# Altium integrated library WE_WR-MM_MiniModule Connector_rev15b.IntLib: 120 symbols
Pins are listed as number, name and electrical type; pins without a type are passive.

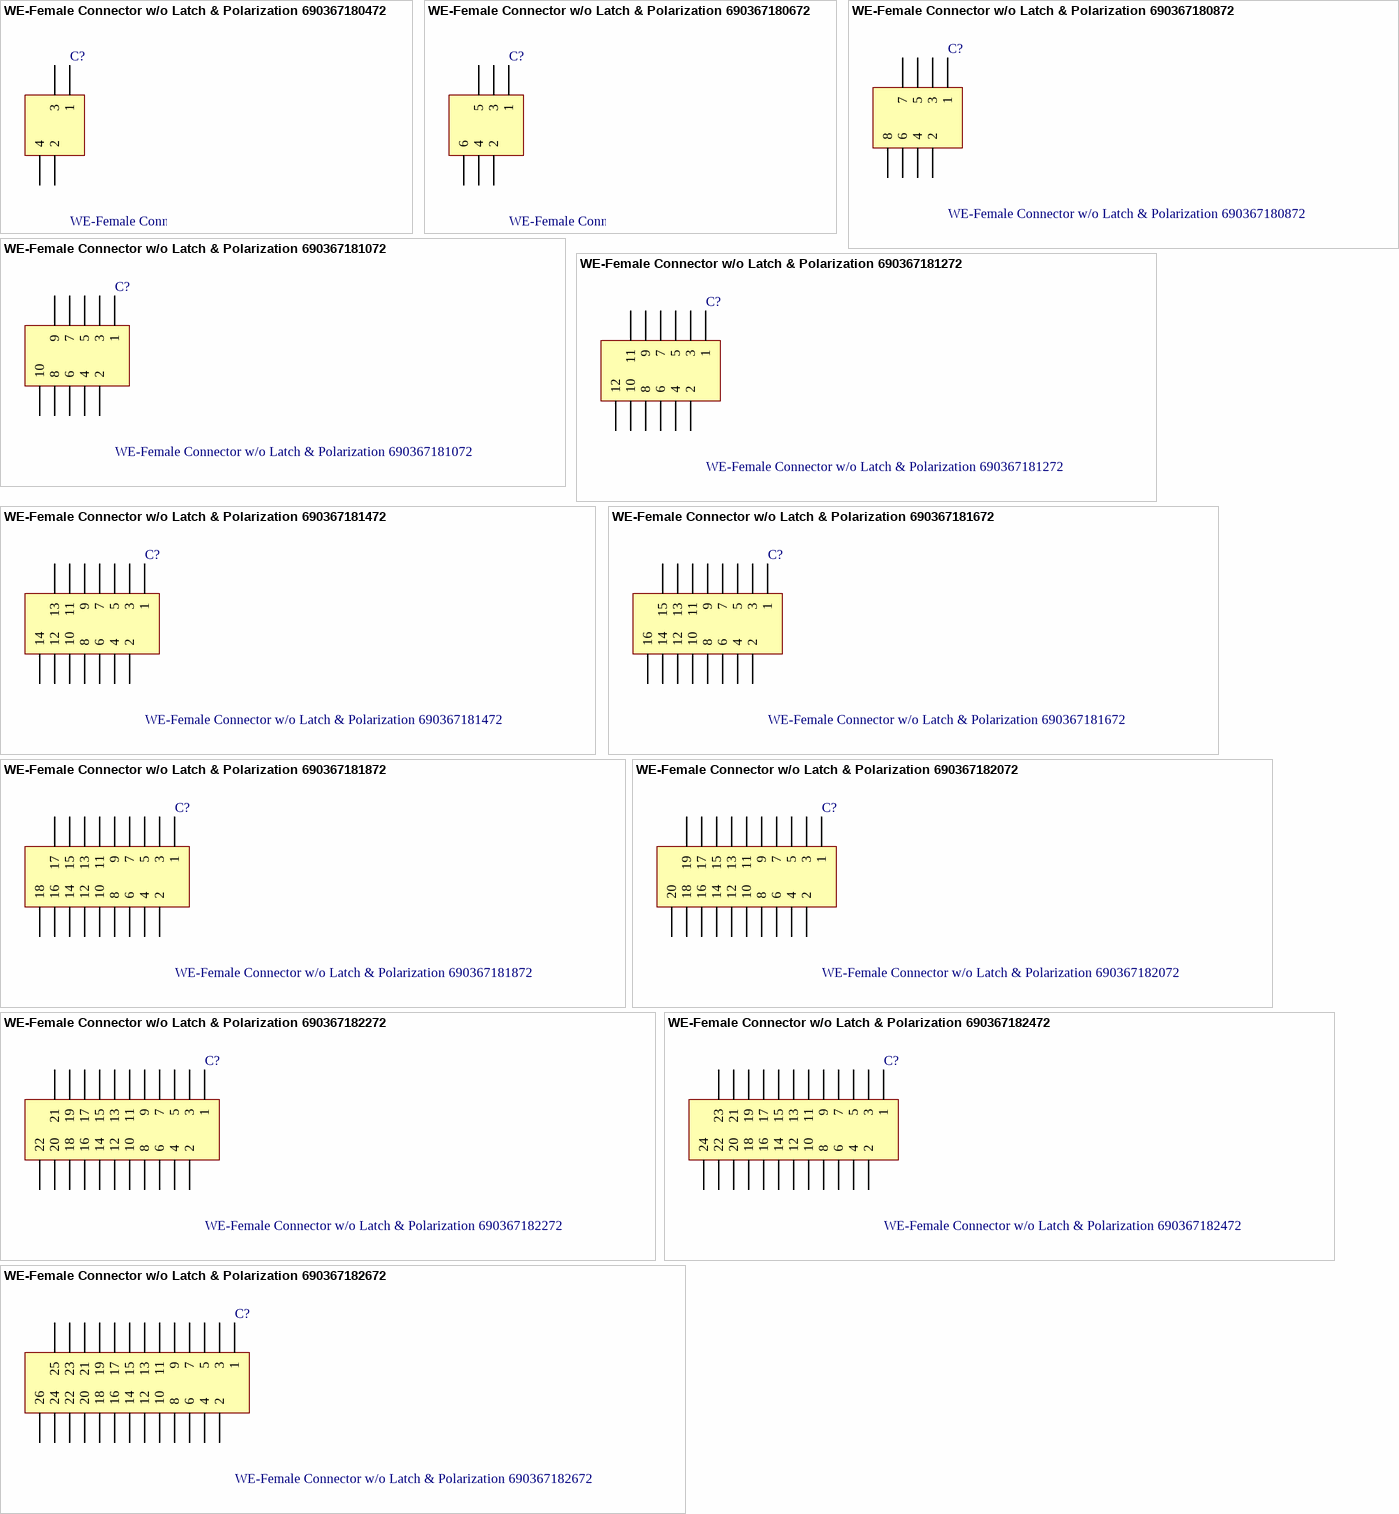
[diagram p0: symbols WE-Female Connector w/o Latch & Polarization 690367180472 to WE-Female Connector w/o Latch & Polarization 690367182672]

## WE-Female Connector w/o Latch & Polarization 690367180472
designator C?
WR-MM Female Connector w/o Latch & Polarization; Manufacturer: Würth Elektronik eiSos GmbH; ComponentLink1 Description: Manufacturer; ComponentLink2 Description: Datasheet; NoPins: 4
footprint 690367180472 (4 pins, straight)
pins: 1, 2, 3, 4

## WE-Female Connector w/o Latch & Polarization 690367180672
designator C?
WR-MM Female Connector w/o Latch & Polarization; Manufacturer: Würth Elektronik eiSos GmbH; ComponentLink1 Description: Manufacturer; ComponentLink2 Description: Datasheet; NoPins: 6
footprint 690367180672 (6 pins, straight)
pins: 1, 2, 3, 4, 5, 6

## WE-Female Connector w/o Latch & Polarization 690367180872
designator C?
WR-MM Female Connector w/o Latch & Polarization; Manufacturer: Würth Elektronik eiSos GmbH; ComponentLink1 Description: Manufacturer; ComponentLink2 Description: Datasheet; NoPins: 8
footprint 690367180872 (8 pins, straight)
pins: 1, 2, 3, 4, 5, 6, 7, 8

## WE-Female Connector w/o Latch & Polarization 690367181072
designator C?
WR-MM Female Connector w/o Latch & Polarization; Manufacturer: Würth Elektronik eiSos GmbH; ComponentLink1 Description: Manufacturer; ComponentLink2 Description: Datasheet; NoPins: 10
footprint 690367181072 (10 pins, straight)
pins: 1, 2, 3, 4, 5, 6, 7, 8, 9, 10

## WE-Female Connector w/o Latch & Polarization 690367181272
designator C?
WR-MM Female Connector w/o Latch & Polarization; Manufacturer: Würth Elektronik eiSos GmbH; ComponentLink1 Description: Manufacturer; ComponentLink2 Description: Datasheet; NoPins: 12
footprint 690367181272 (12 pins, straight)
pins: 1, 2, 3, 4, 5, 6, 7, 8, 9, 10, 11, 12

## WE-Female Connector w/o Latch & Polarization 690367181472
designator C?
WR-MM Female Connector w/o Latch & Polarization; Manufacturer: Würth Elektronik eiSos GmbH; ComponentLink1 Description: Manufacturer; ComponentLink2 Description: Datasheet; NoPins: 14
footprint 690367181472 (14 pins, straight)
pins: 1, 2, 3, 4, 5, 6, 7, 8, 9, 10, 11, 12, 13, 14

## WE-Female Connector w/o Latch & Polarization 690367181672
designator C?
WR-MM Female Connector w/o Latch & Polarization; Manufacturer: Würth Elektronik eiSos GmbH; ComponentLink1 Description: Manufacturer; ComponentLink2 Description: Datasheet; NoPins: 16
footprint 690367181672 (16 pins, straight)
pins: 1, 2, 3, 4, 5, 6, 7, 8, 9, 10, 11, 12, 13, 14, 15, 16

## WE-Female Connector w/o Latch & Polarization 690367181872
designator C?
WR-MM Female Connector w/o Latch & Polarization; Manufacturer: Würth Elektronik eiSos GmbH; ComponentLink1 Description: Manufacturer; ComponentLink2 Description: Datasheet; NoPins: 18
footprint 690367181872 (18 pins, straight)
pins: 1, 2, 3, 4, 5, 6, 7, 8, 9, 10, 11, 12, 13, 14, 15, 16, 17, 18

## WE-Female Connector w/o Latch & Polarization 690367182072
designator C?
WR-MM Female Connector w/o Latch & Polarization; Manufacturer: Würth Elektronik eiSos GmbH; ComponentLink1 Description: Manufacturer; ComponentLink2 Description: Datasheet; NoPins: 20
footprint 690367182072 (20 pins, straight)
pins: 1, 2, 3, 4, 5, 6, 7, 8, 9, 10, 11, 12, 13, 14, 15, 16, 17, 18, 19, 20

## WE-Female Connector w/o Latch & Polarization 690367182272
designator C?
WR-MM Female Connector w/o Latch & Polarization; Manufacturer: Würth Elektronik eiSos GmbH; ComponentLink1 Description: Manufacturer; ComponentLink2 Description: Datasheet; NoPins: 22
footprint 690367182272 (22 pins, straight)
pins: 1, 2, 3, 4, 5, 6, 7, 8, 9, 10, 11, 12, 13, 14, 15, 16, 17, 18, 19, 20, 21, 22

## WE-Female Connector w/o Latch & Polarization 690367182472
designator C?
WR-MM Female Connector w/o Latch & Polarization; Manufacturer: Würth Elektronik eiSos GmbH; ComponentLink1 Description: Manufacturer; ComponentLink2 Description: Datasheet; NoPins: 24
footprint 690367182472 (24 pins, straight)
pins: 1, 2, 3, 4, 5, 6, 7, 8, 9, 10, 11, 12, 13, 14, 15, 16, 17, 18, 19, 20, 21, 22, 23, 24

## WE-Female Connector w/o Latch & Polarization 690367182672
designator C?
WR-MM Female Connector w/o Latch & Polarization; Manufacturer: Würth Elektronik eiSos GmbH; ComponentLink1 Description: Manufacturer; ComponentLink2 Description: Datasheet; NoPins: 26
footprint 690367182672 (26 pins, straight)
pins: 1, 2, 3, 4, 5, 6, 7, 8, 9, 10, 11, 12, 13, 14, 15, 16, 17, 18, 19, 20, 21, 22, 23, 24, 25, 26


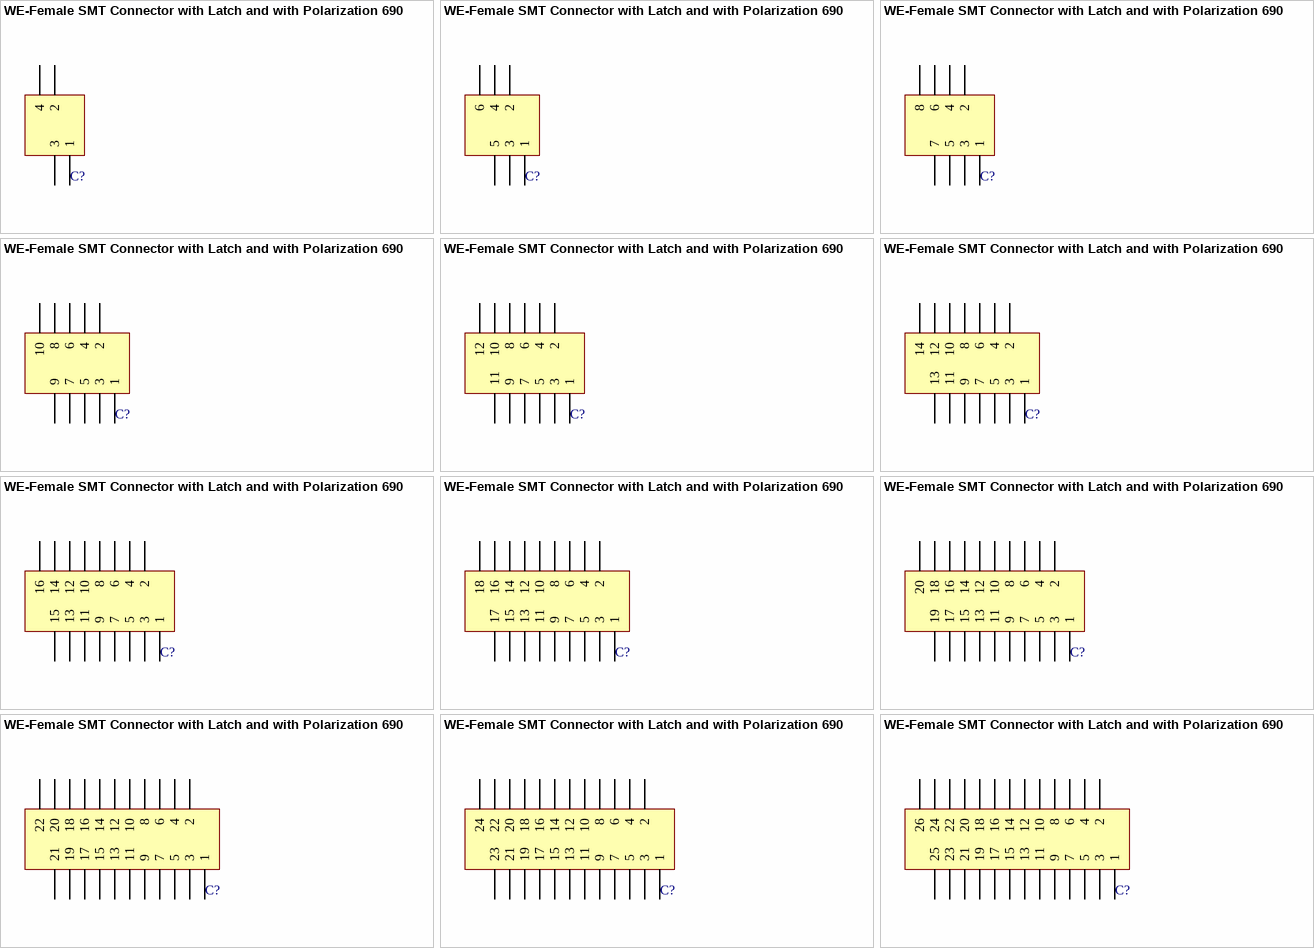
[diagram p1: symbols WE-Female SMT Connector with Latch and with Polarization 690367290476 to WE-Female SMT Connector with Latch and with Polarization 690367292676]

## WE-Female SMT Connector with Latch and with Polarization 690367290476
designator C?
WR-MM Female SMT Connector with Latch; Manufacturer: Würth Elektronik eiSos GmbH; ComponentLink1 Description: Manufacturer; ComponentLink2 Description: Datasheet; NoPins: 4
footprint 690367290476 (and Polarization, 4 pins, SMT, straight)
pins: 1, 2, 3, 4

## WE-Female SMT Connector with Latch and with Polarization 690367290676
designator C?
WR-MM Female SMT Connector with Latch; Manufacturer: Würth Elektronik eiSos GmbH; ComponentLink1 Description: Manufacturer; ComponentLink2 Description: Datasheet; NoPins: 06
footprint 690367290676 (and Polarization, 6 pins, SMT, straight)
pins: 1, 2, 3, 4, 5, 6

## WE-Female SMT Connector with Latch and with Polarization 690367290876
designator C?
WR-MM Female SMT Connector with Latch; Manufacturer: Würth Elektronik eiSos GmbH; ComponentLink1 Description: Manufacturer; ComponentLink2 Description: Datasheet; NoPins: 08
footprint 690367290876 (and Polarization, 8 pins, SMT, straight)
pins: 1, 2, 3, 4, 5, 6, 7, 8

## WE-Female SMT Connector with Latch and with Polarization 690367291076
designator C?
WR-MM Female SMT Connector with Latch; Manufacturer: Würth Elektronik eiSos GmbH; ComponentLink1 Description: Manufacturer; ComponentLink2 Description: Datasheet; NoPins: 10
footprint 690367291076 (and Polarization, 10 pins, SMT, straight)
pins: 1, 2, 3, 4, 5, 6, 7, 8, 9, 10

## WE-Female SMT Connector with Latch and with Polarization 690367291276
designator C?
WR-MM Female SMT Connector with Latch; Manufacturer: Würth Elektronik eiSos GmbH; ComponentLink1 Description: Manufacturer; ComponentLink2 Description: Datasheet; NoPins: 12
footprint 690367291276 (and Polarization, 12 pins, SMT, straight)
pins: 1, 2, 3, 4, 5, 6, 7, 8, 9, 10, 11, 12

## WE-Female SMT Connector with Latch and with Polarization 690367291476
designator C?
WR-MM Female SMT Connector with Latch; Manufacturer: Würth Elektronik eiSos GmbH; ComponentLink1 Description: Manufacturer; ComponentLink2 Description: Datasheet; NoPins: 14
footprint 690367291476 (and Polarization, 14 pins, SMT, straight)
pins: 1, 2, 3, 4, 5, 6, 7, 8, 9, 10, 11, 12, 13, 14

## WE-Female SMT Connector with Latch and with Polarization 690367291676
designator C?
WR-MM Female SMT Connector with Latch; Manufacturer: Würth Elektronik eiSos GmbH; ComponentLink1 Description: Manufacturer; ComponentLink2 Description: Datasheet; NoPins: 16
footprint 690367291676 (and Polarization, 16 pins, SMT, straight)
pins: 1, 2, 3, 4, 5, 6, 7, 8, 9, 10, 11, 12, 13, 14, 15, 16

## WE-Female SMT Connector with Latch and with Polarization 690367291876
designator C?
WR-MM Female SMT Connector with Latch; Manufacturer: Würth Elektronik eiSos GmbH; ComponentLink1 Description: Manufacturer; ComponentLink2 Description: Datasheet; NoPins: 18
footprint 690367291876 (and Polarization, 18 pins, SMT, straight)
pins: 1, 2, 3, 4, 5, 6, 7, 8, 9, 10, 11, 12, 13, 14, 15, 16, 17, 18

## WE-Female SMT Connector with Latch and with Polarization 690367292076
designator C?
WR-MM Female SMT Connector with Latch; Manufacturer: Würth Elektronik eiSos GmbH; ComponentLink1 Description: Manufacturer; ComponentLink2 Description: Datasheet; NoPins: 20
footprint 690367292076 (and Polarization, 20 pins, SMT, straight)
pins: 1, 2, 3, 4, 5, 6, 7, 8, 9, 10, 11, 12, 13, 14, 15, 16, 17, 18, 19, 20

## WE-Female SMT Connector with Latch and with Polarization 690367292276
designator C?
WR-MM Female SMT Connector with Latch; Manufacturer: Würth Elektronik eiSos GmbH; ComponentLink1 Description: Manufacturer; ComponentLink2 Description: Datasheet; NoPins: 22
footprint 690367292276 (and Polarization, 22 pins, SMT, straight)
pins: 1, 2, 3, 4, 5, 6, 7, 8, 9, 10, 11, 12, 13, 14, 15, 16, 17, 18, 19, 20, 21, 22

## WE-Female SMT Connector with Latch and with Polarization 690367292476
designator C?
WR-MM Female SMT Connector with Latch; Manufacturer: Würth Elektronik eiSos GmbH; ComponentLink1 Description: Manufacturer; ComponentLink2 Description: Datasheet; NoPins: 24
footprint 690367292476 (and Polarization, 24 pins, SMT, straight)
pins: 1, 2, 3, 4, 5, 6, 7, 8, 9, 10, 11, 12, 13, 14, 15, 16, 17, 18, 19, 20, 21, 22, 23, 24

## WE-Female SMT Connector with Latch and with Polarization 690367292676
designator C?
WR-MM Female SMT Connector with Latch; Manufacturer: Würth Elektronik eiSos GmbH; ComponentLink1 Description: Manufacturer; ComponentLink2 Description: Datasheet; NoPins: 26
footprint 690367292676 (and Polarization, 26 pins, SMT, straight)
pins: 1, 2, 3, 4, 5, 6, 7, 8, 9, 10, 11, 12, 13, 14, 15, 16, 17, 18, 19, 20, 21, 22, 23, 24, 25, 26


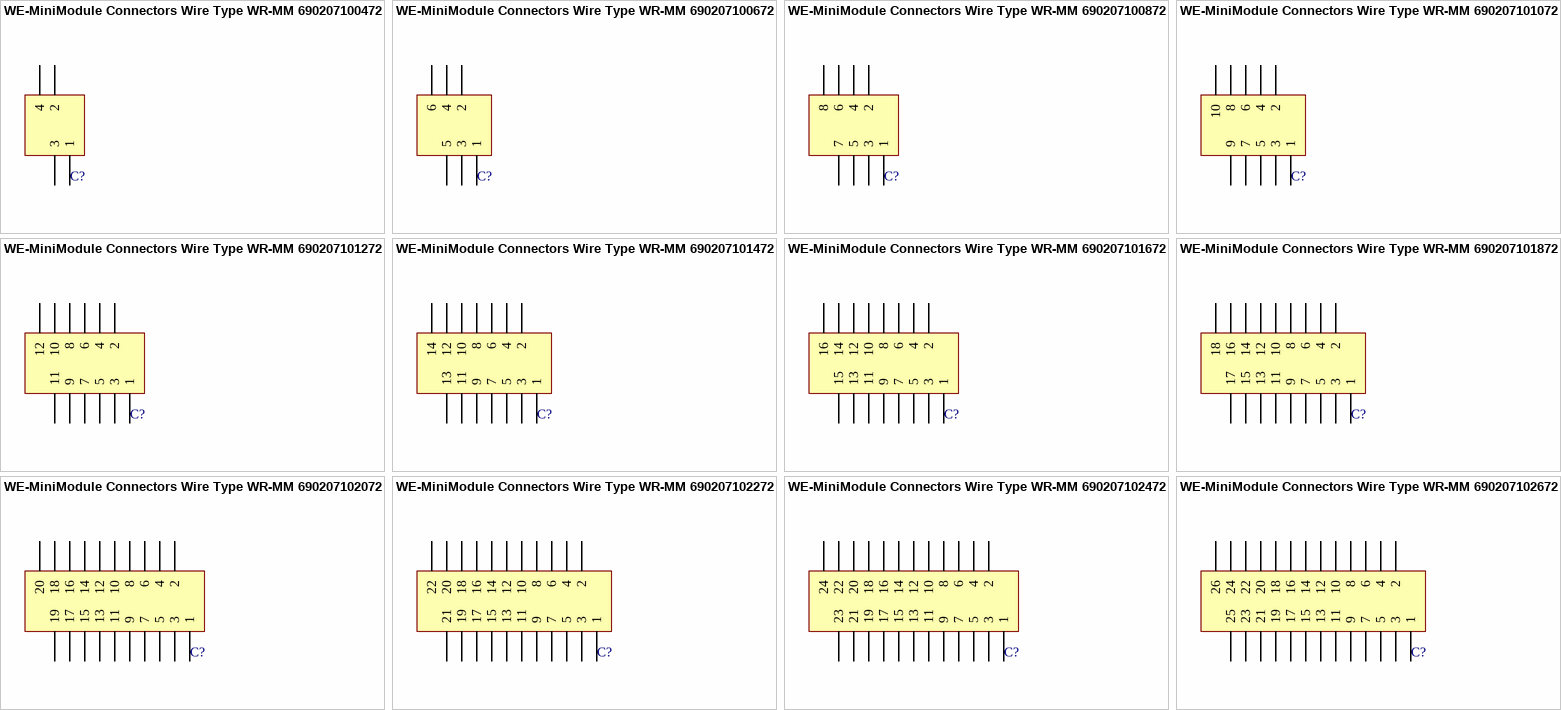
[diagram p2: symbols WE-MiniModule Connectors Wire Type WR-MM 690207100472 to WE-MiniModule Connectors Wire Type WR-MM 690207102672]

## WE-MiniModule Connectors Wire Type WR-MM 690207100472
designator C?
WR-MM Transition Connector; Manufacturer: Würth Elektronik eiSos GmbH; ComponentLink1 Description: Manufacturer; ComponentLink2 Description: Datasheet; NoPins: 4
footprint 690207100472 (4 pins)
pins: 1, 2, 3, 4

## WE-MiniModule Connectors Wire Type WR-MM 690207100672
designator C?
WR-MM Transition Connector; Manufacturer: Würth Elektronik eiSos GmbH; ComponentLink1 Description: Manufacturer; ComponentLink2 Description: Datasheet; NoPins: 6
footprint 690207100672 (6 pins)
pins: 1, 2, 3, 4, 5, 6

## WE-MiniModule Connectors Wire Type WR-MM 690207100872
designator C?
WR-MM Transition Connector; Manufacturer: Würth Elektronik eiSos GmbH; ComponentLink1 Description: Manufacturer; ComponentLink2 Description: Datasheet; NoPins: 8
footprint 690207100872 (8 pins)
pins: 1, 2, 3, 4, 5, 6, 7, 8

## WE-MiniModule Connectors Wire Type WR-MM 690207101072
designator C?
WR-MM Transition Connector; Manufacturer: Würth Elektronik eiSos GmbH; ComponentLink1 Description: Manufacturer; ComponentLink2 Description: Datasheet; NoPins: 10
footprint 690207101072 (10 pins)
pins: 1, 2, 3, 4, 5, 6, 7, 8, 9, 10

## WE-MiniModule Connectors Wire Type WR-MM 690207101272
designator C?
WR-MM Transition Connector; Manufacturer: Würth Elektronik eiSos GmbH; ComponentLink1 Description: Manufacturer; ComponentLink2 Description: Datasheet; NoPins: 12
footprint 690207101272 (12 pins)
pins: 1, 2, 3, 4, 5, 6, 7, 8, 9, 10, 11, 12

## WE-MiniModule Connectors Wire Type WR-MM 690207101472
designator C?
WR-MM Transition Connector; Manufacturer: Würth Elektronik eiSos GmbH; ComponentLink1 Description: Manufacturer; ComponentLink2 Description: Datasheet; NoPins: 14
footprint 690207101472 (14 pins)
pins: 1, 2, 3, 4, 5, 6, 7, 8, 9, 10, 11, 12, 13, 14

## WE-MiniModule Connectors Wire Type WR-MM 690207101672
designator C?
WR-MM Transition Connector; Manufacturer: Würth Elektronik eiSos GmbH; ComponentLink1 Description: Manufacturer; ComponentLink2 Description: Datasheet; NoPins: 16
footprint 690207101672 (16 pins)
pins: 1, 2, 3, 4, 5, 6, 7, 8, 9, 10, 11, 12, 13, 14, 15, 16

## WE-MiniModule Connectors Wire Type WR-MM 690207101872
designator C?
WR-MM Transition Connector; Manufacturer: Würth Elektronik eiSos GmbH; ComponentLink1 Description: Manufacturer; ComponentLink2 Description: Datasheet; NoPins: 18
footprint 690207101872 (18 pins)
pins: 1, 2, 3, 4, 5, 6, 7, 8, 9, 10, 11, 12, 13, 14, 15, 16, 17, 18

## WE-MiniModule Connectors Wire Type WR-MM 690207102072
designator C?
WR-MM Transition Connector; Manufacturer: Würth Elektronik eiSos GmbH; ComponentLink1 Description: Manufacturer; ComponentLink2 Description: Datasheet; NoPins: 20
footprint 690207102072 (20 pins)
pins: 1, 2, 3, 4, 5, 6, 7, 8, 9, 10, 11, 12, 13, 14, 15, 16, 17, 18, 19, 20

## WE-MiniModule Connectors Wire Type WR-MM 690207102272
designator C?
WR-MM Transition Connector; Manufacturer: Würth Elektronik eiSos GmbH; ComponentLink1 Description: Manufacturer; ComponentLink2 Description: Datasheet; NoPins: 22
footprint 690207102272 (22 pins)
pins: 1, 2, 3, 4, 5, 6, 7, 8, 9, 10, 11, 12, 13, 14, 15, 16, 17, 18, 19, 20, 21, 22

## WE-MiniModule Connectors Wire Type WR-MM 690207102472
designator C?
WR-MM Transition Connector; Manufacturer: Würth Elektronik eiSos GmbH; ComponentLink1 Description: Manufacturer; ComponentLink2 Description: Datasheet; NoPins: 24
footprint 690207102472 (24 pins)
pins: 1, 2, 3, 4, 5, 6, 7, 8, 9, 10, 11, 12, 13, 14, 15, 16, 17, 18, 19, 20, 21, 22, 23, 24

## WE-MiniModule Connectors Wire Type WR-MM 690207102672
designator C?
WR-MM Transition Connector; Manufacturer: Würth Elektronik eiSos GmbH; ComponentLink1 Description: Manufacturer; ComponentLink2 Description: Datasheet; NoPins: 26
footprint 690207102672 (26 pins)
pins: 1, 2, 3, 4, 5, 6, 7, 8, 9, 10, 11, 12, 13, 14, 15, 16, 17, 18, 19, 20, 21, 22, 23, 24, 25, 26


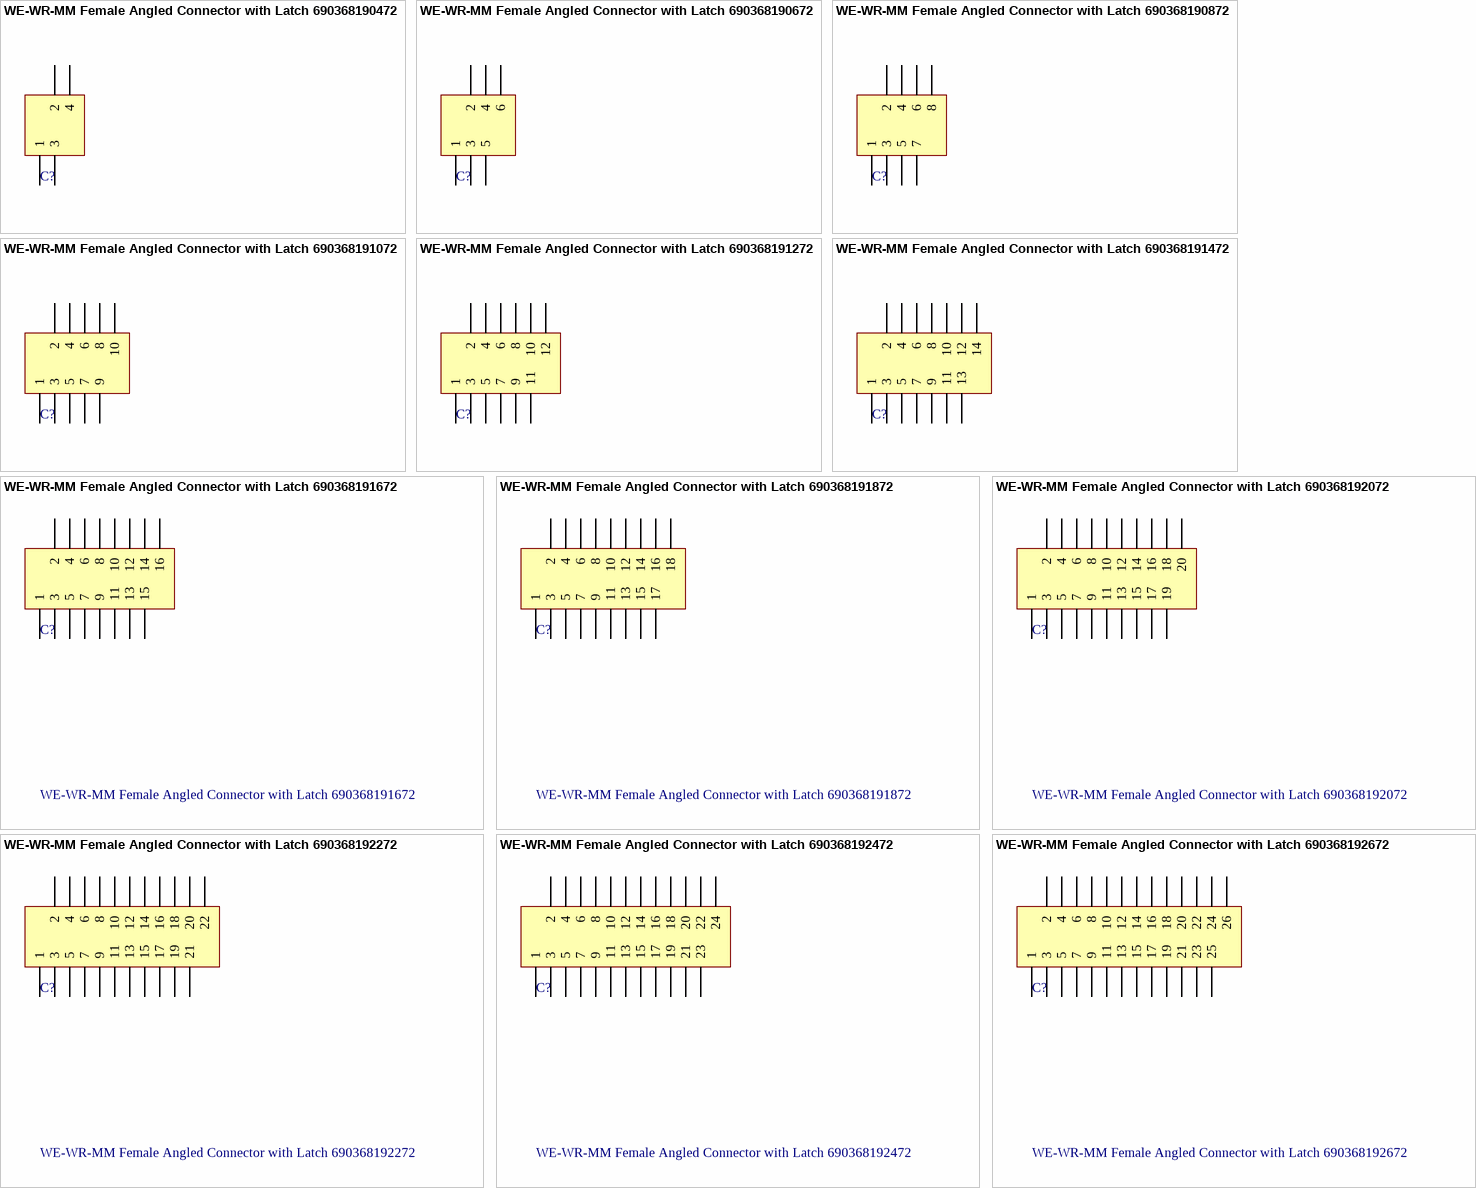
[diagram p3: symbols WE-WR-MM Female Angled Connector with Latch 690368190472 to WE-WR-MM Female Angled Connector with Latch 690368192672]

## WE-WR-MM Female Angled Connector with Latch 690368190472
designator C?
WR-MM Female Angled Connector with Latch; Manufacturer: Würth Elektronik eiSos GmbH; ComponentLink1 Description: Manufacturer; ComponentLink2 Description: Datasheet; NoPins: 4
footprint 690368190472 (and Polarization, 4 pins, right angled)
pins: 1, 2, 3, 4

## WE-WR-MM Female Angled Connector with Latch 690368190672
designator C?
WR-MM Female Angled Connector with Latch; Manufacturer: Würth Elektronik eiSos GmbH; ComponentLink1 Description: Manufacturer; ComponentLink2 Description: Datasheet; NoPins: 6
footprint 690368190672 (and Polarization, 6 pins, right angled)
pins: 1, 2, 3, 4, 5, 6

## WE-WR-MM Female Angled Connector with Latch 690368190872
designator C?
WR-MM Female Angled Connector with Latch; Manufacturer: Würth Elektronik eiSos GmbH; ComponentLink1 Description: Manufacturer; ComponentLink2 Description: Datasheet; NoPins: 8
footprint 690368190872 (and Polarization, 8 pins, right angled)
pins: 1, 2, 3, 4, 5, 6, 7, 8

## WE-WR-MM Female Angled Connector with Latch 690368191072
designator C?
WR-MM Female Angled Connector with Latch; Manufacturer: Würth Elektronik eiSos GmbH; ComponentLink1 Description: Manufacturer; ComponentLink2 Description: Datasheet; NoPins: 10
footprint 690368191072 (and Polarization, 10 pins, right angled)
pins: 1, 2, 3, 4, 5, 6, 7, 8, 9, 10

## WE-WR-MM Female Angled Connector with Latch 690368191272
designator C?
WR-MM Female Angled Connector with Latch; Manufacturer: Würth Elektronik eiSos GmbH; ComponentLink1 Description: Manufacturer; ComponentLink2 Description: Datasheet; NoPins: 12
footprint 690368191272 (and Polarization, 12 pins, right angled)
pins: 1, 2, 3, 4, 5, 6, 7, 8, 9, 10, 11, 12

## WE-WR-MM Female Angled Connector with Latch 690368191472
designator C?
WR-MM Female Angled Connector with Latch; Manufacturer: Würth Elektronik eiSos GmbH; ComponentLink1 Description: Manufacturer; ComponentLink2 Description: Datasheet; NoPins: 14
footprint 690368191472 (and Polarization, 14 pins, right angled)
pins: 1, 2, 3, 4, 5, 6, 7, 8, 9, 10, 11, 12, 13, 14

## WE-WR-MM Female Angled Connector with Latch 690368191672
designator C?
WR-MM Female Angled Connector with Latch; Manufacturer: Würth Elektronik eiSos GmbH; ComponentLink1 Description: Manufacturer; ComponentLink2 Description: Datasheet; NoPins: 16
footprint 690368191672 (and Polarization, 16 pins, right angled)
pins: 1, 2, 3, 4, 5, 6, 7, 8, 9, 10, 11, 12, 13, 14, 15, 16

## WE-WR-MM Female Angled Connector with Latch 690368191872
designator C?
WR-MM Female Angled Connector with Latch; Manufacturer: Würth Elektronik eiSos GmbH; ComponentLink1 Description: Manufacturer; ComponentLink2 Description: Datasheet; NoPins: 18
footprint 690368191872 (and Polarization, 18 pins, right angled)
pins: 1, 2, 3, 4, 5, 6, 7, 8, 9, 10, 11, 12, 13, 14, 15, 16, 17, 18

## WE-WR-MM Female Angled Connector with Latch 690368192072
designator C?
WR-MM Female Angled Connector with Latch; Manufacturer: Würth Elektronik eiSos GmbH; ComponentLink1 Description: Manufacturer; ComponentLink2 Description: Datasheet; NoPins: 20
footprint 690368192072 (and Polarization, 20 pins, right angled)
pins: 1, 2, 3, 4, 5, 6, 7, 8, 9, 10, 11, 12, 13, 14, 15, 16, 17, 18, 19, 20

## WE-WR-MM Female Angled Connector with Latch 690368192272
designator C?
WR-MM Female Angled Connector with Latch; Manufacturer: Würth Elektronik eiSos GmbH; ComponentLink1 Description: Manufacturer; ComponentLink2 Description: Datasheet; NoPins: 22
footprint 690368192272 (and Polarization, 22 pins, right angled)
pins: 1, 2, 3, 4, 5, 6, 7, 8, 9, 10, 11, 12, 13, 14, 15, 16, 17, 18, 19, 20, 21, 22

## WE-WR-MM Female Angled Connector with Latch 690368192472
designator C?
WR-MM Female Angled Connector with Latch; Manufacturer: Würth Elektronik eiSos GmbH; ComponentLink1 Description: Manufacturer; ComponentLink2 Description: Datasheet; NoPins: 24
footprint 690368192472 (and Polarization, 24 pins, right angled)
pins: 1, 2, 3, 4, 5, 6, 7, 8, 9, 10, 11, 12, 13, 14, 15, 16, 17, 18, 19, 20, 21, 22, 23, 24

## WE-WR-MM Female Angled Connector with Latch 690368192672
designator C?
WR-MM Female Angled Connector with Latch; Manufacturer: Würth Elektronik eiSos GmbH; ComponentLink1 Description: Manufacturer; ComponentLink2 Description: Datasheet; NoPins: 26
footprint 690368192672 (and Polarization, 26 pins, right angled)
pins: 1, 2, 3, 4, 5, 6, 7, 8, 9, 10, 11, 12, 13, 14, 15, 16, 17, 18, 19, 20, 21, 22, 23, 24, 25, 26


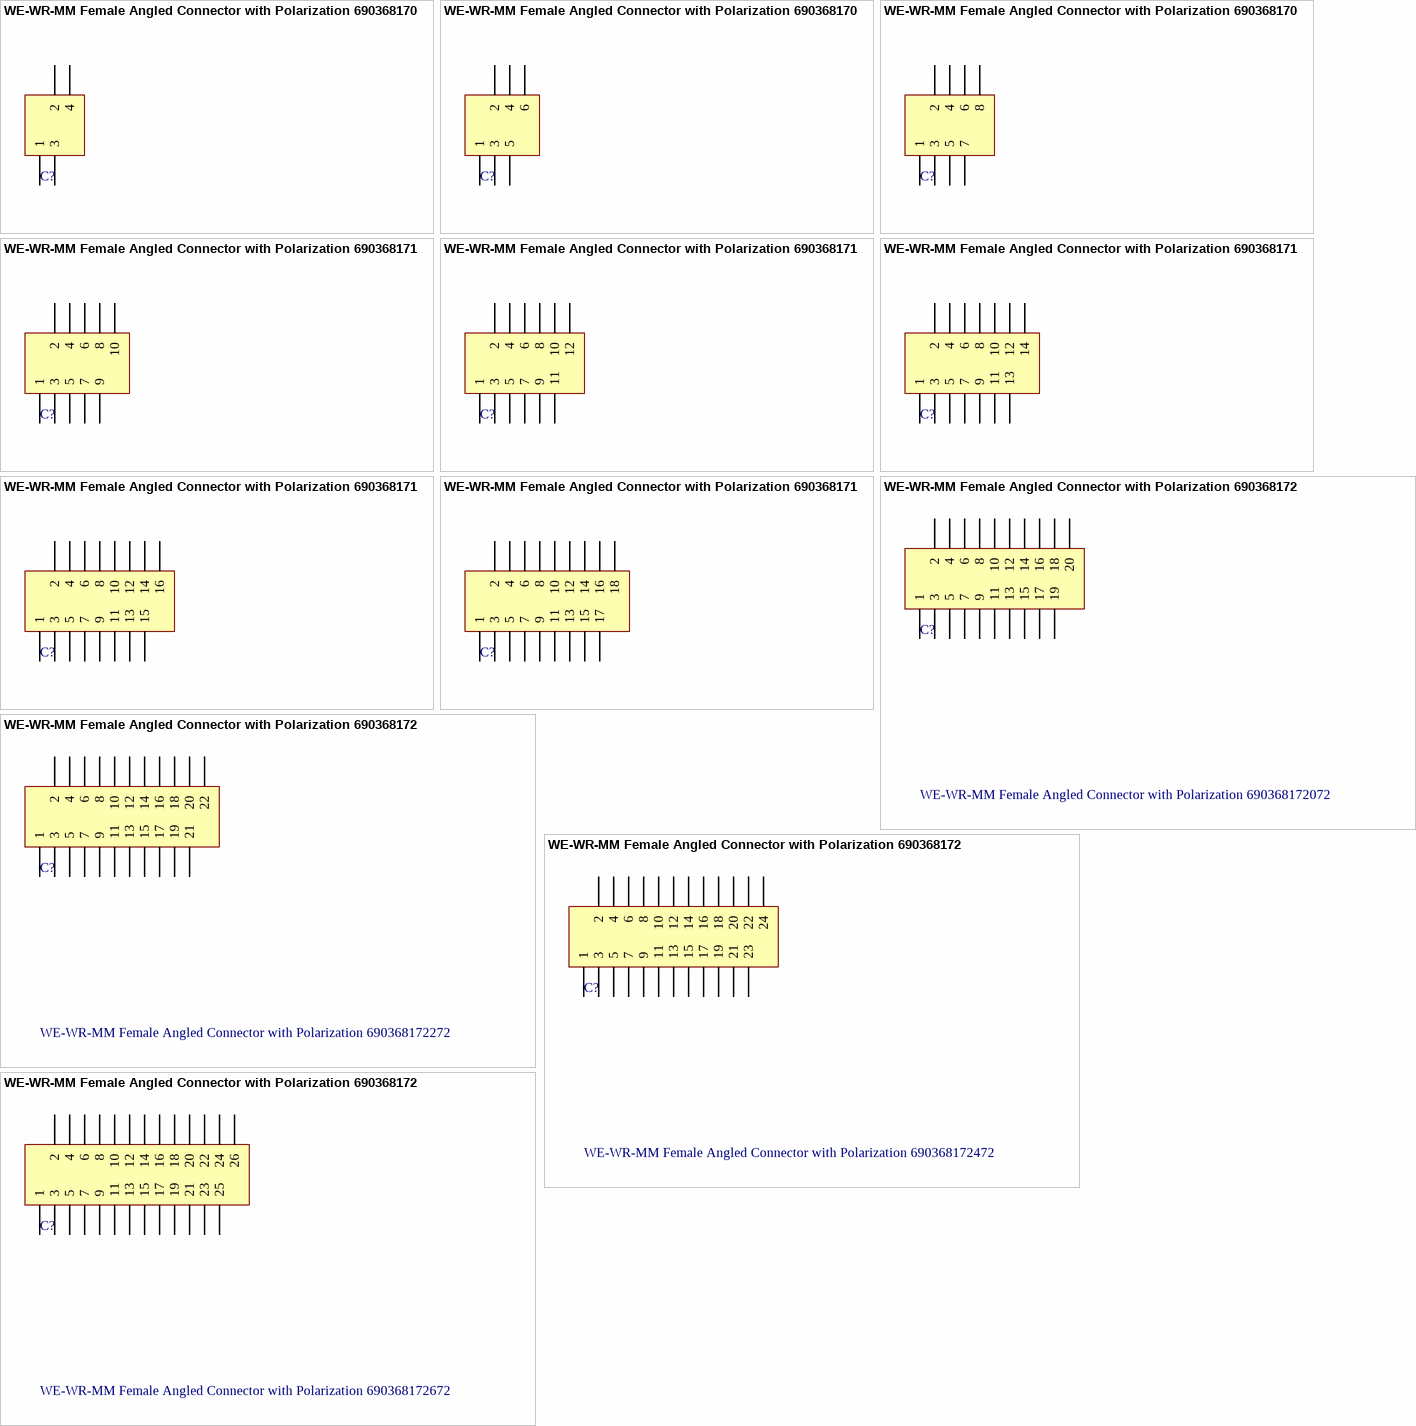
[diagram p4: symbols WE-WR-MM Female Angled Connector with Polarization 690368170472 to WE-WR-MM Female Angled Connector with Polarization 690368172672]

## WE-WR-MM Female Angled Connector with Polarization 690368170472
designator C?
WR-MM Female Angled Connector with Polarization; Manufacturer: Würth Elektronik eiSos GmbH; ComponentLink1 Description: Manufacturer; ComponentLink2 Description: Datasheet; NoPins: 4
footprint 690368170472 (without Latch, 4 pins, right angled)
pins: 1, 2, 3, 4

## WE-WR-MM Female Angled Connector with Polarization 690368170672
designator C?
WR-MM Female Angled Connector with Polarization; Manufacturer: Würth Elektronik eiSos GmbH; ComponentLink1 Description: Manufacturer; ComponentLink2 Description: Datasheet; NoPins: 6
footprint 690368170672 (without Latch, 6 pins, right angled)
pins: 1, 2, 3, 4, 5, 6

## WE-WR-MM Female Angled Connector with Polarization 690368170872
designator C?
WR-MM Female Angled Connector with Polarization; Manufacturer: Würth Elektronik eiSos GmbH; ComponentLink1 Description: Manufacturer; ComponentLink2 Description: Datasheet; NoPins: 8
footprint 690368170872 (without Latch, 8 pins, right angled)
pins: 1, 2, 3, 4, 5, 6, 7, 8

## WE-WR-MM Female Angled Connector with Polarization 690368171072
designator C?
WR-MM Female Angled Connector with Polarization; Manufacturer: Würth Elektronik eiSos GmbH; ComponentLink1 Description: Manufacturer; ComponentLink2 Description: Datasheet; NoPins: 10
footprint 690368171072 (without Latch, 10 pins, right angled)
pins: 1, 2, 3, 4, 5, 6, 7, 8, 9, 10

## WE-WR-MM Female Angled Connector with Polarization 690368171272
designator C?
WR-MM Female Angled Connector with Polarization; Manufacturer: Würth Elektronik eiSos GmbH; ComponentLink1 Description: Manufacturer; ComponentLink2 Description: Datasheet; NoPins: 12
footprint 690368171272 (without Latch, 12 pins, right angled)
pins: 1, 2, 3, 4, 5, 6, 7, 8, 9, 10, 11, 12

## WE-WR-MM Female Angled Connector with Polarization 690368171472
designator C?
WR-MM Female Angled Connector with Polarization; Manufacturer: Würth Elektronik eiSos GmbH; ComponentLink1 Description: Manufacturer; ComponentLink2 Description: Datasheet; NoPins: 14
footprint 690368171472 (without Latch, 14 pins, right angled)
pins: 1, 2, 3, 4, 5, 6, 7, 8, 9, 10, 11, 12, 13, 14

## WE-WR-MM Female Angled Connector with Polarization 690368171672
designator C?
WR-MM Female Angled Connector with Polarization; Manufacturer: Würth Elektronik eiSos GmbH; ComponentLink1 Description: Manufacturer; ComponentLink2 Description: Datasheet; NoPins: 16
footprint 690368171672 (without Latch, 16 pins, right angled)
pins: 1, 2, 3, 4, 5, 6, 7, 8, 9, 10, 11, 12, 13, 14, 15, 16

## WE-WR-MM Female Angled Connector with Polarization 690368171872
designator C?
WR-MM Female Angled Connector with Polarization; Manufacturer: Würth Elektronik eiSos GmbH; ComponentLink1 Description: Manufacturer; ComponentLink2 Description: Datasheet; NoPins: 18
footprint 690368171872 (without Latch, 18 pins, right angled)
pins: 1, 2, 3, 4, 5, 6, 7, 8, 9, 10, 11, 12, 13, 14, 15, 16, 17, 18

## WE-WR-MM Female Angled Connector with Polarization 690368172072
designator C?
WR-MM Female Angled Connector with Polarization; Manufacturer: Würth Elektronik eiSos GmbH; ComponentLink1 Description: Manufacturer; ComponentLink2 Description: Datasheet; NoPins: 20
footprint 690368172072 (without Latch, 20 pins, right angled)
pins: 1, 2, 3, 4, 5, 6, 7, 8, 9, 10, 11, 12, 13, 14, 15, 16, 17, 18, 19, 20

## WE-WR-MM Female Angled Connector with Polarization 690368172272
designator C?
WR-MM Female Angled Connector with Polarization; Manufacturer: Würth Elektronik eiSos GmbH; ComponentLink1 Description: Manufacturer; ComponentLink2 Description: Datasheet; NoPins: 22
footprint 690368172272 (without Latch, 22 pins, right angled)
pins: 1, 2, 3, 4, 5, 6, 7, 8, 9, 10, 11, 12, 13, 14, 15, 16, 17, 18, 19, 20, 21, 22

## WE-WR-MM Female Angled Connector with Polarization 690368172472
designator C?
WR-MM Female Angled Connector with Polarization; Manufacturer: Würth Elektronik eiSos GmbH; ComponentLink1 Description: Manufacturer; ComponentLink2 Description: Datasheet; NoPins: 24
footprint 690368172472 (without Latch, 24 pins, right angled)
pins: 1, 2, 3, 4, 5, 6, 7, 8, 9, 10, 11, 12, 13, 14, 15, 16, 17, 18, 19, 20, 21, 22, 23, 24

## WE-WR-MM Female Angled Connector with Polarization 690368172672
designator C?
WR-MM Female Angled Connector with Polarization; Manufacturer: Würth Elektronik eiSos GmbH; ComponentLink1 Description: Manufacturer; ComponentLink2 Description: Datasheet; NoPins: 26
footprint 690368172672 (without Latch, 26 pins, right angled)
pins: 1, 2, 3, 4, 5, 6, 7, 8, 9, 10, 11, 12, 13, 14, 15, 16, 17, 18, 19, 20, 21, 22, 23, 24, 25, 26


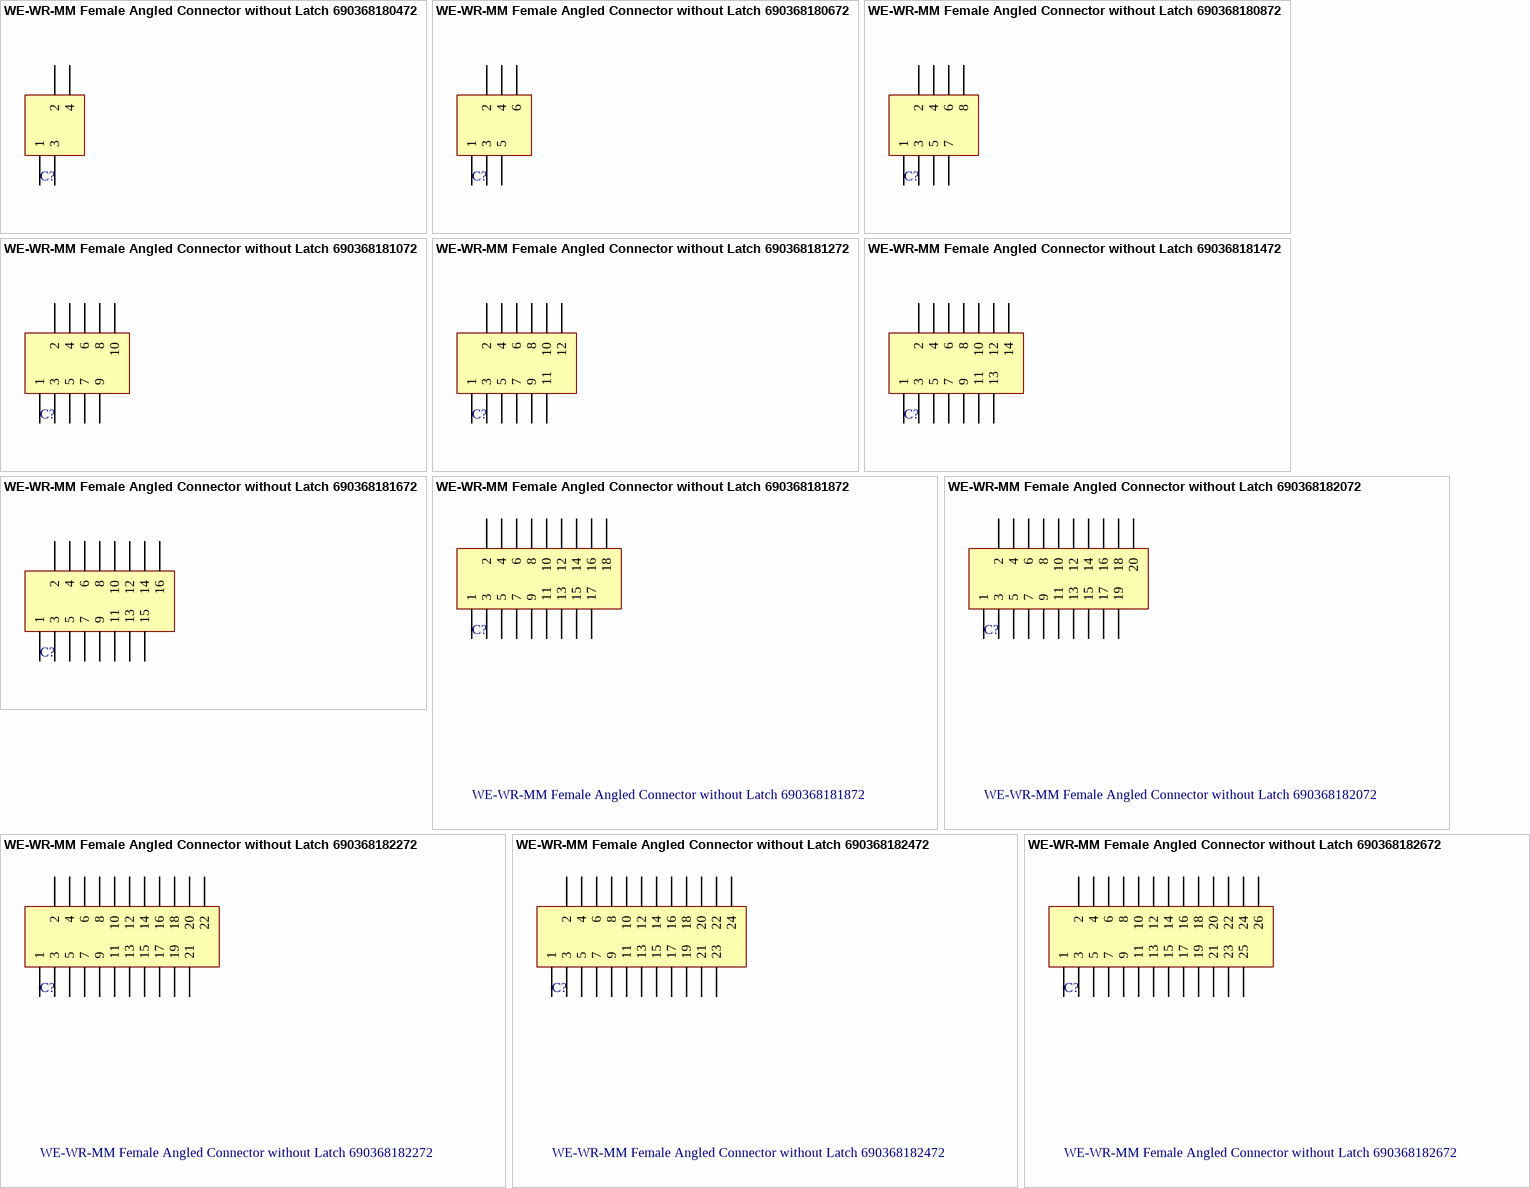
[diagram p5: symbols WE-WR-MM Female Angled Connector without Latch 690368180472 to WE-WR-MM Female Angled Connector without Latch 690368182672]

## WE-WR-MM Female Angled Connector without Latch 690368180472
designator C?
WR-MM Female Angled Connector without Latch; Manufacturer: Würth Elektronik eiSos GmbH; ComponentLink1 Description: Manufacturer; ComponentLink2 Description: Datasheet; NoPins: 4
footprint 690368180472 (without Polarization, 4 pins, right angled)
pins: 1, 2, 3, 4

## WE-WR-MM Female Angled Connector without Latch 690368180672
designator C?
WR-MM Female Angled Connector without Latch; Manufacturer: Würth Elektronik eiSos GmbH; ComponentLink1 Description: Manufacturer; ComponentLink2 Description: Datasheet; NoPins: 6
footprint 690368180672 (without Polarization, 6 pins, right angled)
pins: 1, 2, 3, 4, 5, 6

## WE-WR-MM Female Angled Connector without Latch 690368180872
designator C?
WR-MM Female Angled Connector without Latch; Manufacturer: Würth Elektronik eiSos GmbH; ComponentLink1 Description: Manufacturer; ComponentLink2 Description: Datasheet; NoPins: 8
footprint 690368180872 (without Polarization, 8 pins, right angled)
pins: 1, 2, 3, 4, 5, 6, 7, 8

## WE-WR-MM Female Angled Connector without Latch 690368181072
designator C?
WR-MM Female Angled Connector without Latch; Manufacturer: Würth Elektronik eiSos GmbH; ComponentLink1 Description: Manufacturer; ComponentLink2 Description: Datasheet; NoPins: 10
footprint 690368181072 (without Polarization, 10 pins, right angled)
pins: 1, 2, 3, 4, 5, 6, 7, 8, 9, 10

## WE-WR-MM Female Angled Connector without Latch 690368181272
designator C?
WR-MM Female Angled Connector without Latch; Manufacturer: Würth Elektronik eiSos GmbH; ComponentLink1 Description: Manufacturer; ComponentLink2 Description: Datasheet; NoPins: 12
footprint 690368181272 (without Polarization, 12 pins, right angled)
pins: 1, 2, 3, 4, 5, 6, 7, 8, 9, 10, 11, 12

## WE-WR-MM Female Angled Connector without Latch 690368181472
designator C?
WR-MM Female Angled Connector without Latch; Manufacturer: Würth Elektronik eiSos GmbH; ComponentLink1 Description: Manufacturer; ComponentLink2 Description: Datasheet; NoPins: 14
footprint 690368181472 (without Polarization,14 pins, right angled)
pins: 1, 2, 3, 4, 5, 6, 7, 8, 9, 10, 11, 12, 13, 14

## WE-WR-MM Female Angled Connector without Latch 690368181672
designator C?
WR-MM Female Angled Connector without Latch; Manufacturer: Würth Elektronik eiSos GmbH; ComponentLink1 Description: Manufacturer; ComponentLink2 Description: Datasheet; NoPins: 16
footprint 690368181672 (without Polarization, 16 pins, right angled)
pins: 1, 2, 3, 4, 5, 6, 7, 8, 9, 10, 11, 12, 13, 14, 15, 16

## WE-WR-MM Female Angled Connector without Latch 690368181872
designator C?
WR-MM Female Angled Connector without Latch; Manufacturer: Würth Elektronik eiSos GmbH; ComponentLink1 Description: Manufacturer; ComponentLink2 Description: Datasheet; NoPins: 18
footprint 690368181872 (without Polarization, 18 pins, right angled)
pins: 1, 2, 3, 4, 5, 6, 7, 8, 9, 10, 11, 12, 13, 14, 15, 16, 17, 18

## WE-WR-MM Female Angled Connector without Latch 690368182072
designator C?
WR-MM Female Angled Connector without Latch; Manufacturer: Würth Elektronik eiSos GmbH; ComponentLink1 Description: Manufacturer; ComponentLink2 Description: Datasheet; NoPins: 20
footprint 690368182072 (without Polarization, 20 pins, right angled)
pins: 1, 2, 3, 4, 5, 6, 7, 8, 9, 10, 11, 12, 13, 14, 15, 16, 17, 18, 19, 20

## WE-WR-MM Female Angled Connector without Latch 690368182272
designator C?
WR-MM Female Angled Connector without Latch; Manufacturer: Würth Elektronik eiSos GmbH; ComponentLink1 Description: Manufacturer; ComponentLink2 Description: Datasheet; NoPins: 22
footprint 690368182272 (without Polarization, 22 pins, right angled)
pins: 1, 2, 3, 4, 5, 6, 7, 8, 9, 10, 11, 12, 13, 14, 15, 16, 17, 18, 19, 20, 21, 22

## WE-WR-MM Female Angled Connector without Latch 690368182472
designator C?
WR-MM Female Angled Connector without Latch; Manufacturer: Würth Elektronik eiSos GmbH; ComponentLink1 Description: Manufacturer; ComponentLink2 Description: Datasheet; NoPins: 24
footprint 690368182472 (without Polarization, 24 pins, right angled)
pins: 1, 2, 3, 4, 5, 6, 7, 8, 9, 10, 11, 12, 13, 14, 15, 16, 17, 18, 19, 20, 21, 22, 23, 24

## WE-WR-MM Female Angled Connector without Latch 690368182672
designator C?
WR-MM Female Angled Connector without Latch; Manufacturer: Würth Elektronik eiSos GmbH; ComponentLink1 Description: Manufacturer; ComponentLink2 Description: Datasheet; NoPins: 26
footprint 690368182672 (without Polarization, 26 pins, right angled)
pins: 1, 2, 3, 4, 5, 6, 7, 8, 9, 10, 11, 12, 13, 14, 15, 16, 17, 18, 19, 20, 21, 22, 23, 24, 25, 26


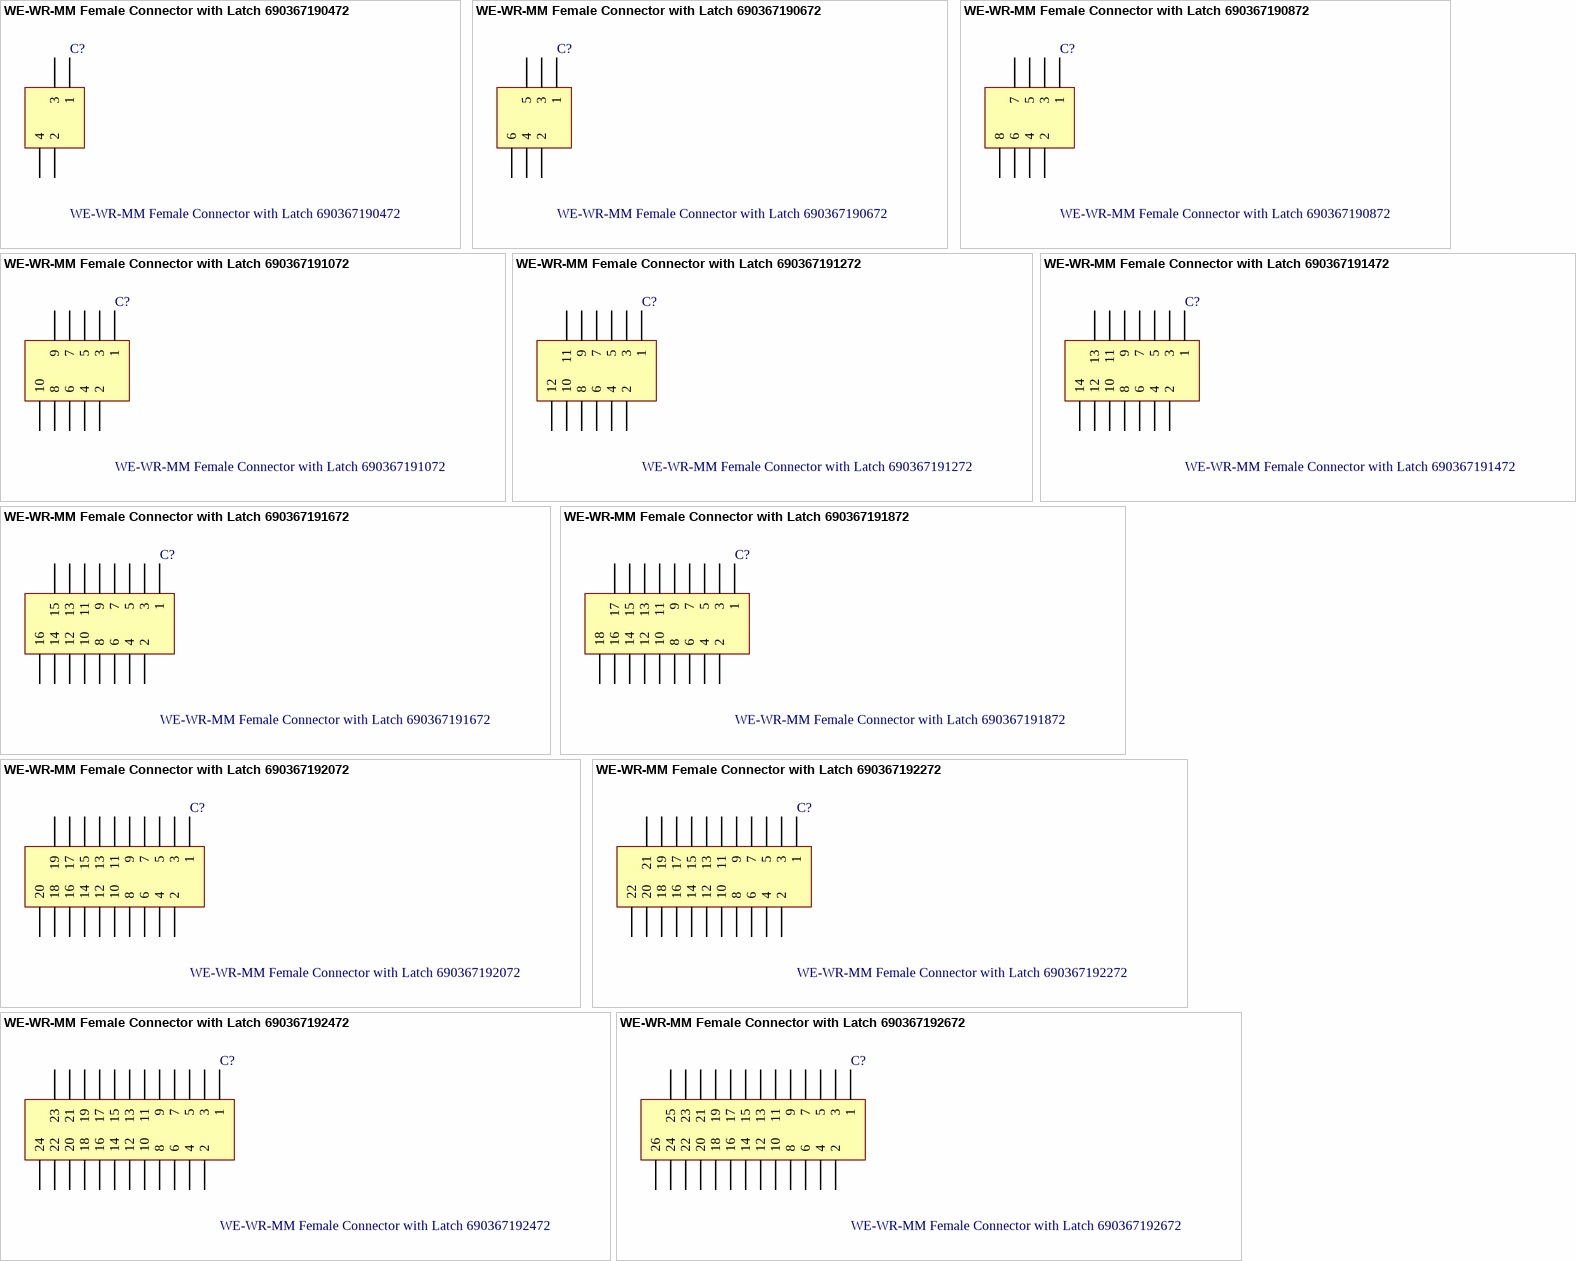
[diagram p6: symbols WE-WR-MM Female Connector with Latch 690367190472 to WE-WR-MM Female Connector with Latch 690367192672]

## WE-WR-MM Female Connector with Latch 690367190472
designator C?
WR-MM Female Connector with Latch; Manufacturer: Würth Elektronik eiSos GmbH; ComponentLink1 Description: Manufacturer; ComponentLink2 Description: Datasheet; NoPins: 4
footprint 690367190472 (without Polarization, 4 pins, straight)
pins: 1, 2, 3, 4

## WE-WR-MM Female Connector with Latch 690367190672
designator C?
WR-MM Female Connector with Latch; Manufacturer: Würth Elektronik eiSos GmbH; ComponentLink1 Description: Manufacturer; ComponentLink2 Description: Datasheet; NoPins: 6
footprint 690367190672 (without Polarization, 6 pins, straight)
pins: 1, 2, 3, 4, 5, 6

## WE-WR-MM Female Connector with Latch 690367190872
designator C?
WR-MM Female Connector with Latch; Manufacturer: Würth Elektronik eiSos GmbH; ComponentLink1 Description: Manufacturer; ComponentLink2 Description: Datasheet; NoPins: 8
footprint 690367190872 (without Polarization, 8 pins, straight)
pins: 1, 2, 3, 4, 5, 6, 7, 8

## WE-WR-MM Female Connector with Latch 690367191072
designator C?
WR-MM Female Connector with Latch; Manufacturer: Würth Elektronik eiSos GmbH; ComponentLink1 Description: Manufacturer; ComponentLink2 Description: Datasheet; NoPins: 10
footprint 690367191072 (without Polarization, 10 pins, straight)
pins: 1, 2, 3, 4, 5, 6, 7, 8, 9, 10

## WE-WR-MM Female Connector with Latch 690367191272
designator C?
WR-MM Female Connector with Latch; Manufacturer: Würth Elektronik eiSos GmbH; ComponentLink1 Description: Manufacturer; ComponentLink2 Description: Datasheet; NoPins: 12
footprint 690367191272 (without Polarization, 12 pins, straight)
pins: 1, 2, 3, 4, 5, 6, 7, 8, 9, 10, 11, 12

## WE-WR-MM Female Connector with Latch 690367191472
designator C?
WR-MM Female Connector with Latch; Manufacturer: Würth Elektronik eiSos GmbH; ComponentLink1 Description: Manufacturer; ComponentLink2 Description: Datasheet; NoPins: 14
footprint 690367191472 (without Polarization, 14 pins, straight)
pins: 1, 2, 3, 4, 5, 6, 7, 8, 9, 10, 11, 12, 13, 14

## WE-WR-MM Female Connector with Latch 690367191672
designator C?
WR-MM Female Connector with Latch; Manufacturer: Würth Elektronik eiSos GmbH; ComponentLink1 Description: Manufacturer; ComponentLink2 Description: Datasheet; NoPins: 16
footprint 690367191672 (without Polarization, 16 pins, straight)
pins: 1, 2, 3, 4, 5, 6, 7, 8, 9, 10, 11, 12, 13, 14, 15, 16

## WE-WR-MM Female Connector with Latch 690367191872
designator C?
WR-MM Female Connector with Latch; Manufacturer: Würth Elektronik eiSos GmbH; ComponentLink1 Description: Manufacturer; ComponentLink2 Description: Datasheet; NoPins: 18
footprint 690367191872 (without Polarization, 18 pins, straight)
pins: 1, 2, 3, 4, 5, 6, 7, 8, 9, 10, 11, 12, 13, 14, 15, 16, 17, 18

## WE-WR-MM Female Connector with Latch 690367192072
designator C?
WR-MM Female Connector with Latch; Manufacturer: Würth Elektronik eiSos GmbH; ComponentLink1 Description: Manufacturer; ComponentLink2 Description: Datasheet; NoPins: 20
footprint 690367192072 (without Polarization, 20 pins, straight)
pins: 1, 2, 3, 4, 5, 6, 7, 8, 9, 10, 11, 12, 13, 14, 15, 16, 17, 18, 19, 20

## WE-WR-MM Female Connector with Latch 690367192272
designator C?
WR-MM Female Connector with Latch; Manufacturer: Würth Elektronik eiSos GmbH; ComponentLink1 Description: Manufacturer; ComponentLink2 Description: Datasheet; NoPins: 22
footprint 690367192272 (without Polarization, 22 pins, straight)
pins: 1, 2, 3, 4, 5, 6, 7, 8, 9, 10, 11, 12, 13, 14, 15, 16, 17, 18, 19, 20, 21, 22

## WE-WR-MM Female Connector with Latch 690367192472
designator C?
WR-MM Female Connector with Latch; Manufacturer: Würth Elektronik eiSos GmbH; ComponentLink1 Description: Manufacturer; ComponentLink2 Description: Datasheet; NoPins: 24
footprint 690367192472 (without Polarization, 24 pins, straight)
pins: 1, 2, 3, 4, 5, 6, 7, 8, 9, 10, 11, 12, 13, 14, 15, 16, 17, 18, 19, 20, 21, 22, 23, 24

## WE-WR-MM Female Connector with Latch 690367192672
designator C?
WR-MM Female Connector with Latch; Manufacturer: Würth Elektronik eiSos GmbH; ComponentLink1 Description: Manufacturer; ComponentLink2 Description: Datasheet; NoPins: 26
footprint 690367192672 (without Polarization, 26 pins, straight)
pins: 1, 2, 3, 4, 5, 6, 7, 8, 9, 10, 11, 12, 13, 14, 15, 16, 17, 18, 19, 20, 21, 22, 23, 24, 25, 26


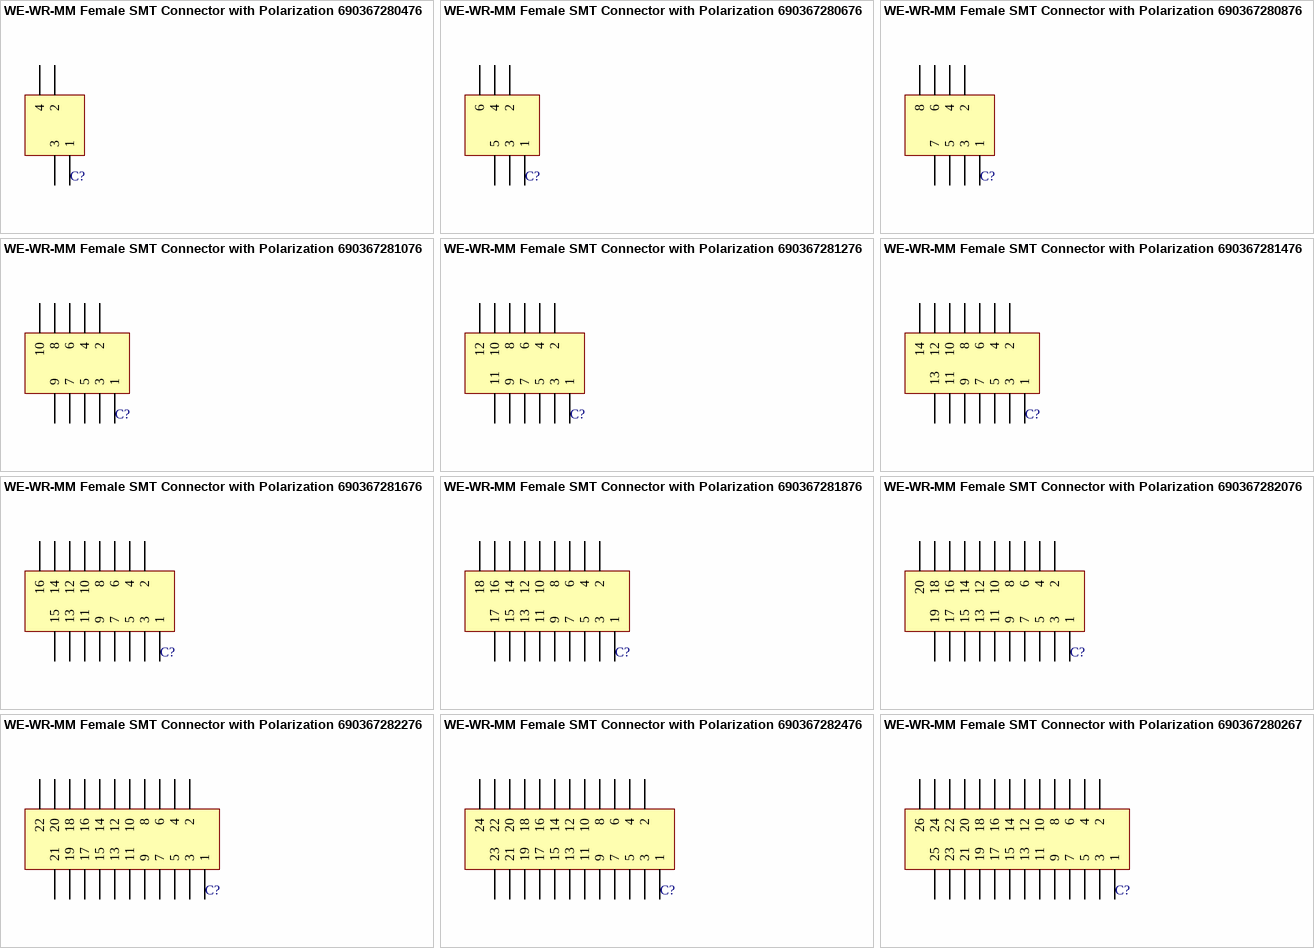
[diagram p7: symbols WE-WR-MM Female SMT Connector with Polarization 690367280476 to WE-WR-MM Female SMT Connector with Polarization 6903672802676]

## WE-WR-MM Female SMT Connector with Polarization 690367280476
designator C?
WR-MM Female SMT Connector with Polarization; Manufacturer: Würth Elektronik eiSos GmbH; ComponentLink1 Description: Manufacturer; ComponentLink2 Description: Datasheet; NoPins: 4
footprint 690367280476 (without Latch, 4 pins, SMT, straight)
pins: 1, 2, 3, 4

## WE-WR-MM Female SMT Connector with Polarization 690367280676
designator C?
WR-MM Female SMT Connector with Polarization; Manufacturer: Würth Elektronik eiSos GmbH; ComponentLink1 Description: Manufacturer; ComponentLink2 Description: Datasheet; NoPins: 6
footprint 690367280676 (without Latch, 6 pins, SMT, straight)
pins: 1, 2, 3, 4, 5, 6

## WE-WR-MM Female SMT Connector with Polarization 690367280876
designator C?
WR-MM Female SMT Connector with Polarization; Manufacturer: Würth Elektronik eiSos GmbH; ComponentLink1 Description: Manufacturer; ComponentLink2 Description: Datasheet; NoPins: 8
footprint 690367280876 (without Latch, 8 pins, SMT, straight)
pins: 1, 2, 3, 4, 5, 6, 7, 8

## WE-WR-MM Female SMT Connector with Polarization 690367281076
designator C?
WR-MM Female SMT Connector with Polarization; Manufacturer: Würth Elektronik eiSos GmbH; ComponentLink1 Description: Manufacturer; ComponentLink2 Description: Datasheet; NoPins: 10
footprint 690367281076 (without Latch, 10 pins, SMT, straight)
pins: 1, 2, 3, 4, 5, 6, 7, 8, 9, 10

## WE-WR-MM Female SMT Connector with Polarization 690367281276
designator C?
WR-MM Female SMT Connector with Polarization; Manufacturer: Würth Elektronik eiSos GmbH; ComponentLink1 Description: Manufacturer; ComponentLink2 Description: Datasheet; NoPins: 12
footprint 690367281276 (without Latch, 12 pins, SMT, straight)
pins: 1, 2, 3, 4, 5, 6, 7, 8, 9, 10, 11, 12

## WE-WR-MM Female SMT Connector with Polarization 690367281476
designator C?
WR-MM Female SMT Connector with Polarization; Manufacturer: Würth Elektronik eiSos GmbH; ComponentLink1 Description: Manufacturer; ComponentLink2 Description: Datasheet; NoPins: 14
footprint 690367281476 (without Latch, 14 pins, SMT, straight)
pins: 1, 2, 3, 4, 5, 6, 7, 8, 9, 10, 11, 12, 13, 14

## WE-WR-MM Female SMT Connector with Polarization 690367281676
designator C?
WR-MM Female SMT Connector with Polarization; Manufacturer: Würth Elektronik eiSos GmbH; ComponentLink1 Description: Manufacturer; ComponentLink2 Description: Datasheet; NoPins: 16
footprint 690367281676 (without Latch, 16 pins, SMT, straight)
pins: 1, 2, 3, 4, 5, 6, 7, 8, 9, 10, 11, 12, 13, 14, 15, 16

## WE-WR-MM Female SMT Connector with Polarization 690367281876
designator C?
WR-MM Female SMT Connector with Polarization; Manufacturer: Würth Elektronik eiSos GmbH; ComponentLink1 Description: Manufacturer; ComponentLink2 Description: Datasheet; NoPins: 18
footprint 690367281876 (without Latch, 18 pins, SMT, straight)
pins: 1, 2, 3, 4, 5, 6, 7, 8, 9, 10, 11, 12, 13, 14, 15, 16, 17, 18

## WE-WR-MM Female SMT Connector with Polarization 690367282076
designator C?
WR-MM Female SMT Connector with Polarization; Manufacturer: Würth Elektronik eiSos GmbH; ComponentLink1 Description: Manufacturer; ComponentLink2 Description: Datasheet; NoPins: 20
footprint 690367282076 (without Latch, 20 pins, SMT, straight)
pins: 1, 2, 3, 4, 5, 6, 7, 8, 9, 10, 11, 12, 13, 14, 15, 16, 17, 18, 19, 20

## WE-WR-MM Female SMT Connector with Polarization 690367282276
designator C?
WR-MM Female SMT Connector with Polarization; Manufacturer: Würth Elektronik eiSos GmbH; ComponentLink1 Description: Manufacturer; ComponentLink2 Description: Datasheet; NoPins: 22
footprint 690367282276 (without Latch, 22 pins, SMT, straight)
pins: 1, 2, 3, 4, 5, 6, 7, 8, 9, 10, 11, 12, 13, 14, 15, 16, 17, 18, 19, 20, 21, 22

## WE-WR-MM Female SMT Connector with Polarization 690367282476
designator C?
WR-MM Female SMT Connector with Polarization; Manufacturer: Würth Elektronik eiSos GmbH; ComponentLink1 Description: Manufacturer; ComponentLink2 Description: Datasheet; NoPins: 24
footprint 690367282476 (without Latch, 24 pins, SMT, straight)
pins: 1, 2, 3, 4, 5, 6, 7, 8, 9, 10, 11, 12, 13, 14, 15, 16, 17, 18, 19, 20, 21, 22, 23, 24

## WE-WR-MM Female SMT Connector with Polarization 6903672802676
designator C?
WR-MM Female SMT Connector with Polarization; Manufacturer: Würth Elektronik eiSos GmbH; ComponentLink1 Description: Manufacturer; ComponentLink2 Description: Datasheet; NoPins: 26
footprint 690367282676 (without Latch, 26 pins, SMT, straight)
pins: 1, 2, 3, 4, 5, 6, 7, 8, 9, 10, 11, 12, 13, 14, 15, 16, 17, 18, 19, 20, 21, 22, 23, 24, 25, 26


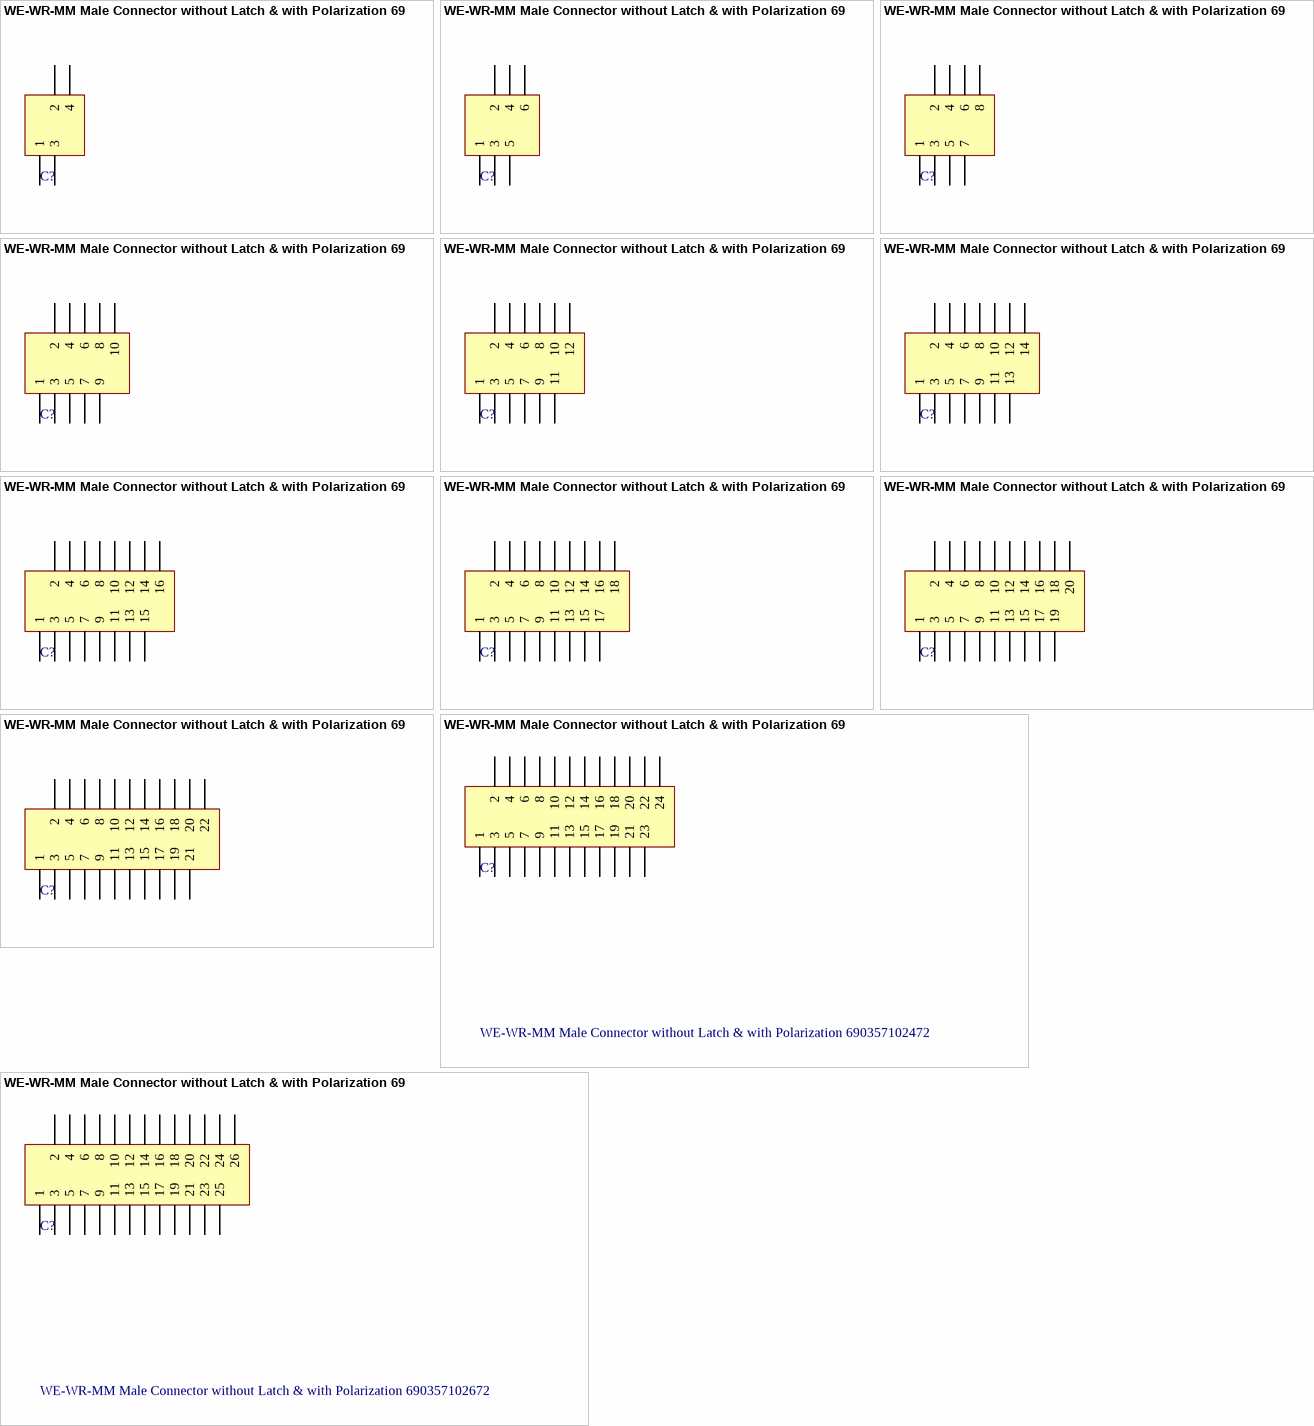
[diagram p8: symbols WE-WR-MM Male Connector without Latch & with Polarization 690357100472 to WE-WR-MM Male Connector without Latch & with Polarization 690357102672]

## WE-WR-MM Male Connector without Latch & with Polarization 690357100472
designator C?
WR-MM Male Connector without Latch & with Polarization; Manufacturer: Würth Elektronik eiSos GmbH; ComponentLink1 Description: Manufacturer; ComponentLink2 Description: Datasheet; NoPins: 4
footprint 690357100472 (4 pins, straight)
pins: 1, 2, 3, 4

## WE-WR-MM Male Connector without Latch & with Polarization 690357100672
designator C?
WR-MM Male Connector without Latch & with Polarization; Manufacturer: Würth Elektronik eiSos GmbH; ComponentLink1 Description: Manufacturer; ComponentLink2 Description: Datasheet; NoPins: 6
footprint 690357100672 (6 pins, straight)
pins: 1, 2, 3, 4, 5, 6

## WE-WR-MM Male Connector without Latch & with Polarization 690357100872
designator C?
WR-MM Male Connector without Latch & with Polarization; Manufacturer: Würth Elektronik eiSos GmbH; ComponentLink1 Description: Manufacturer; ComponentLink2 Description: Datasheet; NoPins: 8
footprint 690357100872 (8 pins, straight)
pins: 1, 2, 3, 4, 5, 6, 7, 8

## WE-WR-MM Male Connector without Latch & with Polarization 690357101072
designator C?
WR-MM Male Connector without Latch & with Polarization; Manufacturer: Würth Elektronik eiSos GmbH; ComponentLink1 Description: Manufacturer; ComponentLink2 Description: Datasheet; NoPins: 10
footprint 690357101072 (10 pins, straight)
pins: 1, 2, 3, 4, 5, 6, 7, 8, 9, 10

## WE-WR-MM Male Connector without Latch & with Polarization 690357101272
designator C?
WR-MM Male Connector without Latch & with Polarization; Manufacturer: Würth Elektronik eiSos GmbH; ComponentLink1 Description: Manufacturer; ComponentLink2 Description: Datasheet; NoPins: 12
footprint 690357101272 (12 pins, straight)
pins: 1, 2, 3, 4, 5, 6, 7, 8, 9, 10, 11, 12

## WE-WR-MM Male Connector without Latch & with Polarization 690357101472
designator C?
WR-MM Male Connector without Latch & with Polarization; Manufacturer: Würth Elektronik eiSos GmbH; ComponentLink1 Description: Manufacturer; ComponentLink2 Description: Datasheet; NoPins: 14
footprint 690357101472 (14 pins, straight)
pins: 1, 2, 3, 4, 5, 6, 7, 8, 9, 10, 11, 12, 13, 14

## WE-WR-MM Male Connector without Latch & with Polarization 690357101672
designator C?
WR-MM Male Connector without Latch & with Polarization; Manufacturer: Würth Elektronik eiSos GmbH; ComponentLink1 Description: Manufacturer; ComponentLink2 Description: Datasheet; NoPins: 16
footprint 690357101672 (16 pins, straight)
pins: 1, 2, 3, 4, 5, 6, 7, 8, 9, 10, 11, 12, 13, 14, 15, 16

## WE-WR-MM Male Connector without Latch & with Polarization 690357101872
designator C?
WR-MM Male Connector without Latch & with Polarization; Manufacturer: Würth Elektronik eiSos GmbH; ComponentLink1 Description: Manufacturer; ComponentLink2 Description: Datasheet; NoPins: 18
footprint 690357101872 (18 pins, straight)
pins: 1, 2, 3, 4, 5, 6, 7, 8, 9, 10, 11, 12, 13, 14, 15, 16, 17, 18

## WE-WR-MM Male Connector without Latch & with Polarization 690357102072
designator C?
WR-MM Male Connector without Latch & with Polarization; Manufacturer: Würth Elektronik eiSos GmbH; ComponentLink1 Description: Manufacturer; ComponentLink2 Description: Datasheet; NoPins: 20
footprint 690357102072 (20 pins, straight)
pins: 1, 2, 3, 4, 5, 6, 7, 8, 9, 10, 11, 12, 13, 14, 15, 16, 17, 18, 19, 20

## WE-WR-MM Male Connector without Latch & with Polarization 690357102272
designator C?
WR-MM Male Connector without Latch & with Polarization; Manufacturer: Würth Elektronik eiSos GmbH; ComponentLink1 Description: Manufacturer; ComponentLink2 Description: Datasheet; NoPins: 22
footprint 690357102272 (22 pins, straight)
pins: 1, 2, 3, 4, 5, 6, 7, 8, 9, 10, 11, 12, 13, 14, 15, 16, 17, 18, 19, 20, 21, 22

## WE-WR-MM Male Connector without Latch & with Polarization 690357102472
designator C?
WR-MM Male Connector without Latch & with Polarization; Manufacturer: Würth Elektronik eiSos GmbH; ComponentLink1 Description: Manufacturer; ComponentLink2 Description: Datasheet; NoPins: 24
footprint 690357102472 (24 pins, straight)
pins: 1, 2, 3, 4, 5, 6, 7, 8, 9, 10, 11, 12, 13, 14, 15, 16, 17, 18, 19, 20, 21, 22, 23, 24

## WE-WR-MM Male Connector without Latch & with Polarization 690357102672
designator C?
WR-MM Male Connector without Latch & with Polarization; Manufacturer: Würth Elektronik eiSos GmbH; ComponentLink1 Description: Manufacturer; ComponentLink2 Description: Datasheet; NoPins: 26
footprint 690357102672 (26 pins, straight)
pins: 1, 2, 3, 4, 5, 6, 7, 8, 9, 10, 11, 12, 13, 14, 15, 16, 17, 18, 19, 20, 21, 22, 23, 24, 25, 26


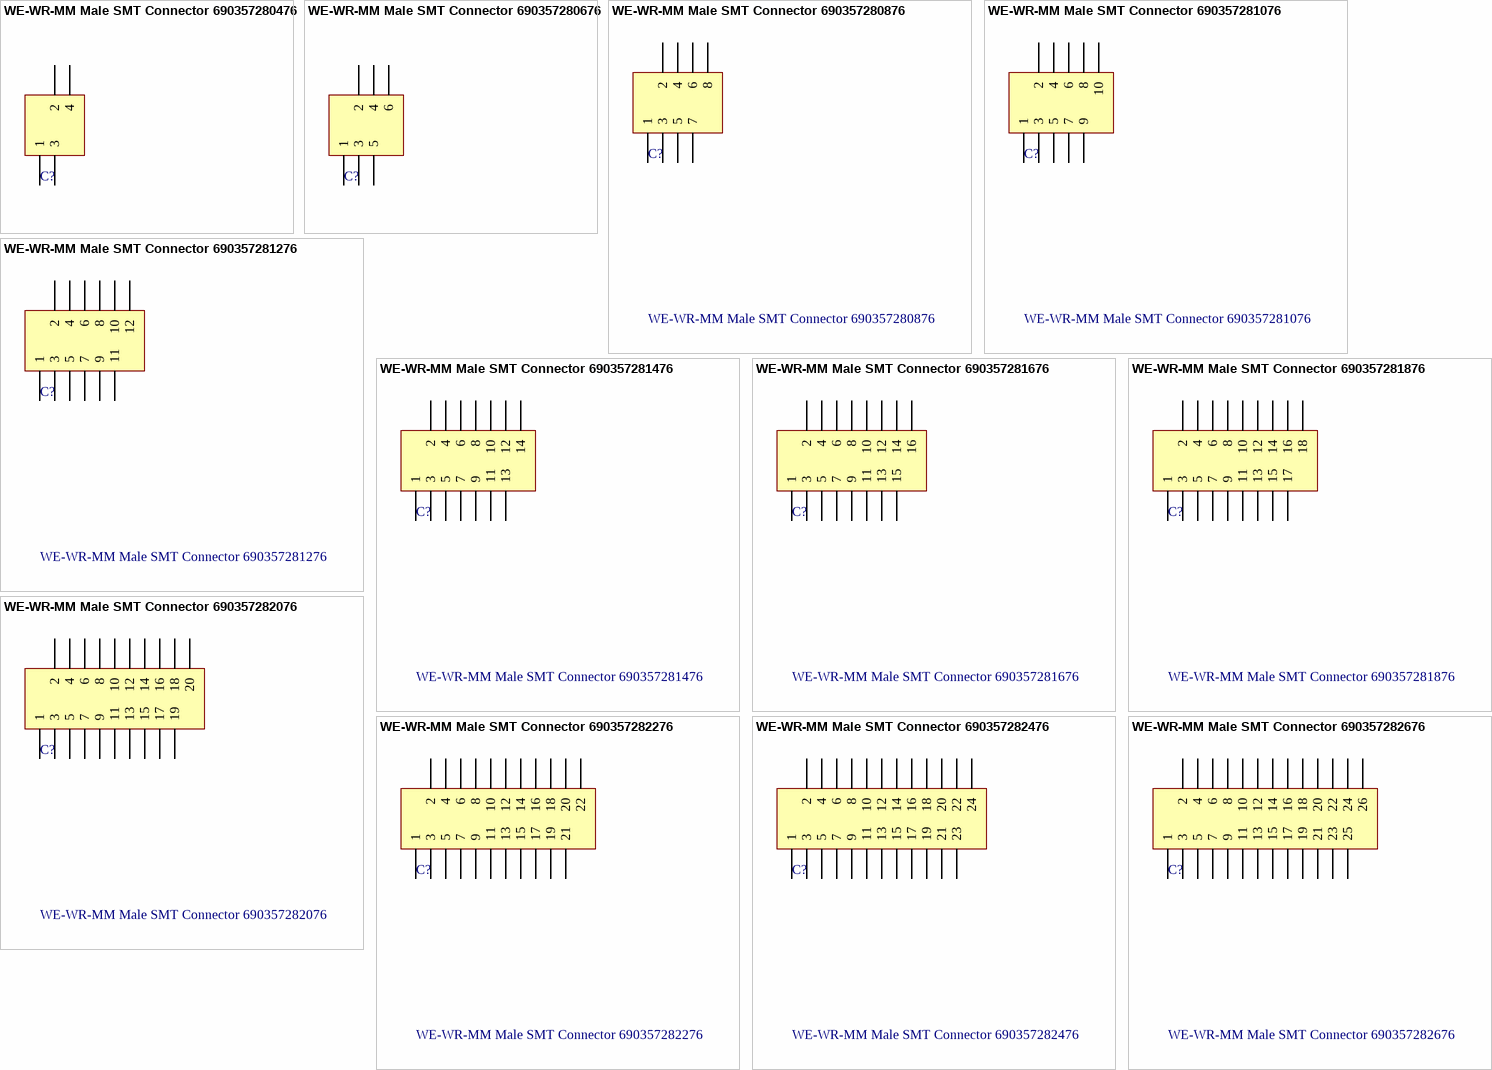
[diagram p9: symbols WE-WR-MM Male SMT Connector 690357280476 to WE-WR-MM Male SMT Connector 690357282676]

## WE-WR-MM Male SMT Connector 690357280476
designator C?
WR-MM Male SMT Connector; Manufacturer: Würth Elektronik eiSos GmbH; ComponentLink1 Description: Manufacturer; ComponentLink2 Description: Datasheet; NoPins: 4
footprint 690357280476 (4 pins, SMT, straight)
pins: 1, 2, 3, 4

## WE-WR-MM Male SMT Connector 690357280676
designator C?
WR-MM Male SMT Connector; Manufacturer: Würth Elektronik eiSos GmbH; ComponentLink1 Description: Manufacturer; ComponentLink2 Description: Datasheet; NoPins: 6
footprint 690357280676 (6 pins, SMT, straight)
pins: 1, 2, 3, 4, 5, 6

## WE-WR-MM Male SMT Connector 690357280876
designator C?
WR-MM Male SMT Connector; Manufacturer: Würth Elektronik eiSos GmbH; ComponentLink1 Description: Manufacturer; ComponentLink2 Description: Datasheet; NoPins: 8
footprint 690357280876 (8 pins, SMT, straight)
pins: 1, 2, 3, 4, 5, 6, 7, 8

## WE-WR-MM Male SMT Connector 690357281076
designator C?
WR-MM Male SMT Connector; Manufacturer: Würth Elektronik eiSos GmbH; ComponentLink1 Description: Manufacturer; ComponentLink2 Description: Datasheet; NoPins: 10
footprint 690357281076 (10 pins, SMT, straight)
pins: 1, 2, 3, 4, 5, 6, 7, 8, 9, 10

## WE-WR-MM Male SMT Connector 690357281276
designator C?
WR-MM Male SMT Connector; Manufacturer: Würth Elektronik eiSos GmbH; ComponentLink1 Description: Manufacturer; ComponentLink2 Description: Datasheet; NoPins: 4
footprint 690357281276 (12 pins, SMT, straight)
pins: 1, 2, 3, 4, 5, 6, 7, 8, 9, 10, 11, 12

## WE-WR-MM Male SMT Connector 690357281476
designator C?
WR-MM Male SMT Connector; Manufacturer: Würth Elektronik eiSos GmbH; ComponentLink1 Description: Manufacturer; ComponentLink2 Description: Datasheet; NoPins: 14
footprint 690357281476 (14 pins, SMT, straight)
pins: 1, 2, 3, 4, 5, 6, 7, 8, 9, 10, 11, 12, 13, 14

## WE-WR-MM Male SMT Connector 690357281676
designator C?
WR-MM Male SMT Connector; Manufacturer: Würth Elektronik eiSos GmbH; ComponentLink1 Description: Manufacturer; ComponentLink2 Description: Datasheet; NoPins: 16
footprint 690357281676 (16 pins, SMT, straight)
pins: 1, 2, 3, 4, 5, 6, 7, 8, 9, 10, 11, 12, 13, 14, 15, 16

## WE-WR-MM Male SMT Connector 690357281876
designator C?
WR-MM Male SMT Connector; Manufacturer: Würth Elektronik eiSos GmbH; ComponentLink1 Description: Manufacturer; ComponentLink2 Description: Datasheet; NoPins: 18
footprint 690357281876 (18 pins, SMT, straight)
pins: 1, 2, 3, 4, 5, 6, 7, 8, 9, 10, 11, 12, 13, 14, 15, 16, 17, 18

## WE-WR-MM Male SMT Connector 690357282076
designator C?
WR-MM Male SMT Connector; Manufacturer: Würth Elektronik eiSos GmbH; ComponentLink1 Description: Manufacturer; ComponentLink2 Description: Datasheet; NoPins: 20
footprint 690357282076 (20 pins, SMT, straight)
pins: 1, 2, 3, 4, 5, 6, 7, 8, 9, 10, 11, 12, 13, 14, 15, 16, 17, 18, 19, 20

## WE-WR-MM Male SMT Connector 690357282276
designator C?
WR-MM Male SMT Connector; Manufacturer: Würth Elektronik eiSos GmbH; ComponentLink1 Description: Manufacturer; ComponentLink2 Description: Datasheet; NoPins: 22
footprint 690357282276 (22 pins, SMT, straight)
pins: 1, 2, 3, 4, 5, 6, 7, 8, 9, 10, 11, 12, 13, 14, 15, 16, 17, 18, 19, 20, 21, 22

## WE-WR-MM Male SMT Connector 690357282476
designator C?
WR-MM Male SMT Connector; Manufacturer: Würth Elektronik eiSos GmbH; ComponentLink1 Description: Manufacturer; ComponentLink2 Description: Datasheet; NoPins: 24
footprint 690357282476 (24 pins, SMT, straight)
pins: 1, 2, 3, 4, 5, 6, 7, 8, 9, 10, 11, 12, 13, 14, 15, 16, 17, 18, 19, 20, 21, 22, 23, 24

## WE-WR-MM Male SMT Connector 690357282676
designator C?
WR-MM Male SMT Connector; Manufacturer: Würth Elektronik eiSos GmbH; ComponentLink1 Description: Manufacturer; ComponentLink2 Description: Datasheet; NoPins: 26
footprint 690357282676 (26 pins, SMT, straight)
pins: 1, 2, 3, 4, 5, 6, 7, 8, 9, 10, 11, 12, 13, 14, 15, 16, 17, 18, 19, 20, 21, 22, 23, 24, 25, 26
